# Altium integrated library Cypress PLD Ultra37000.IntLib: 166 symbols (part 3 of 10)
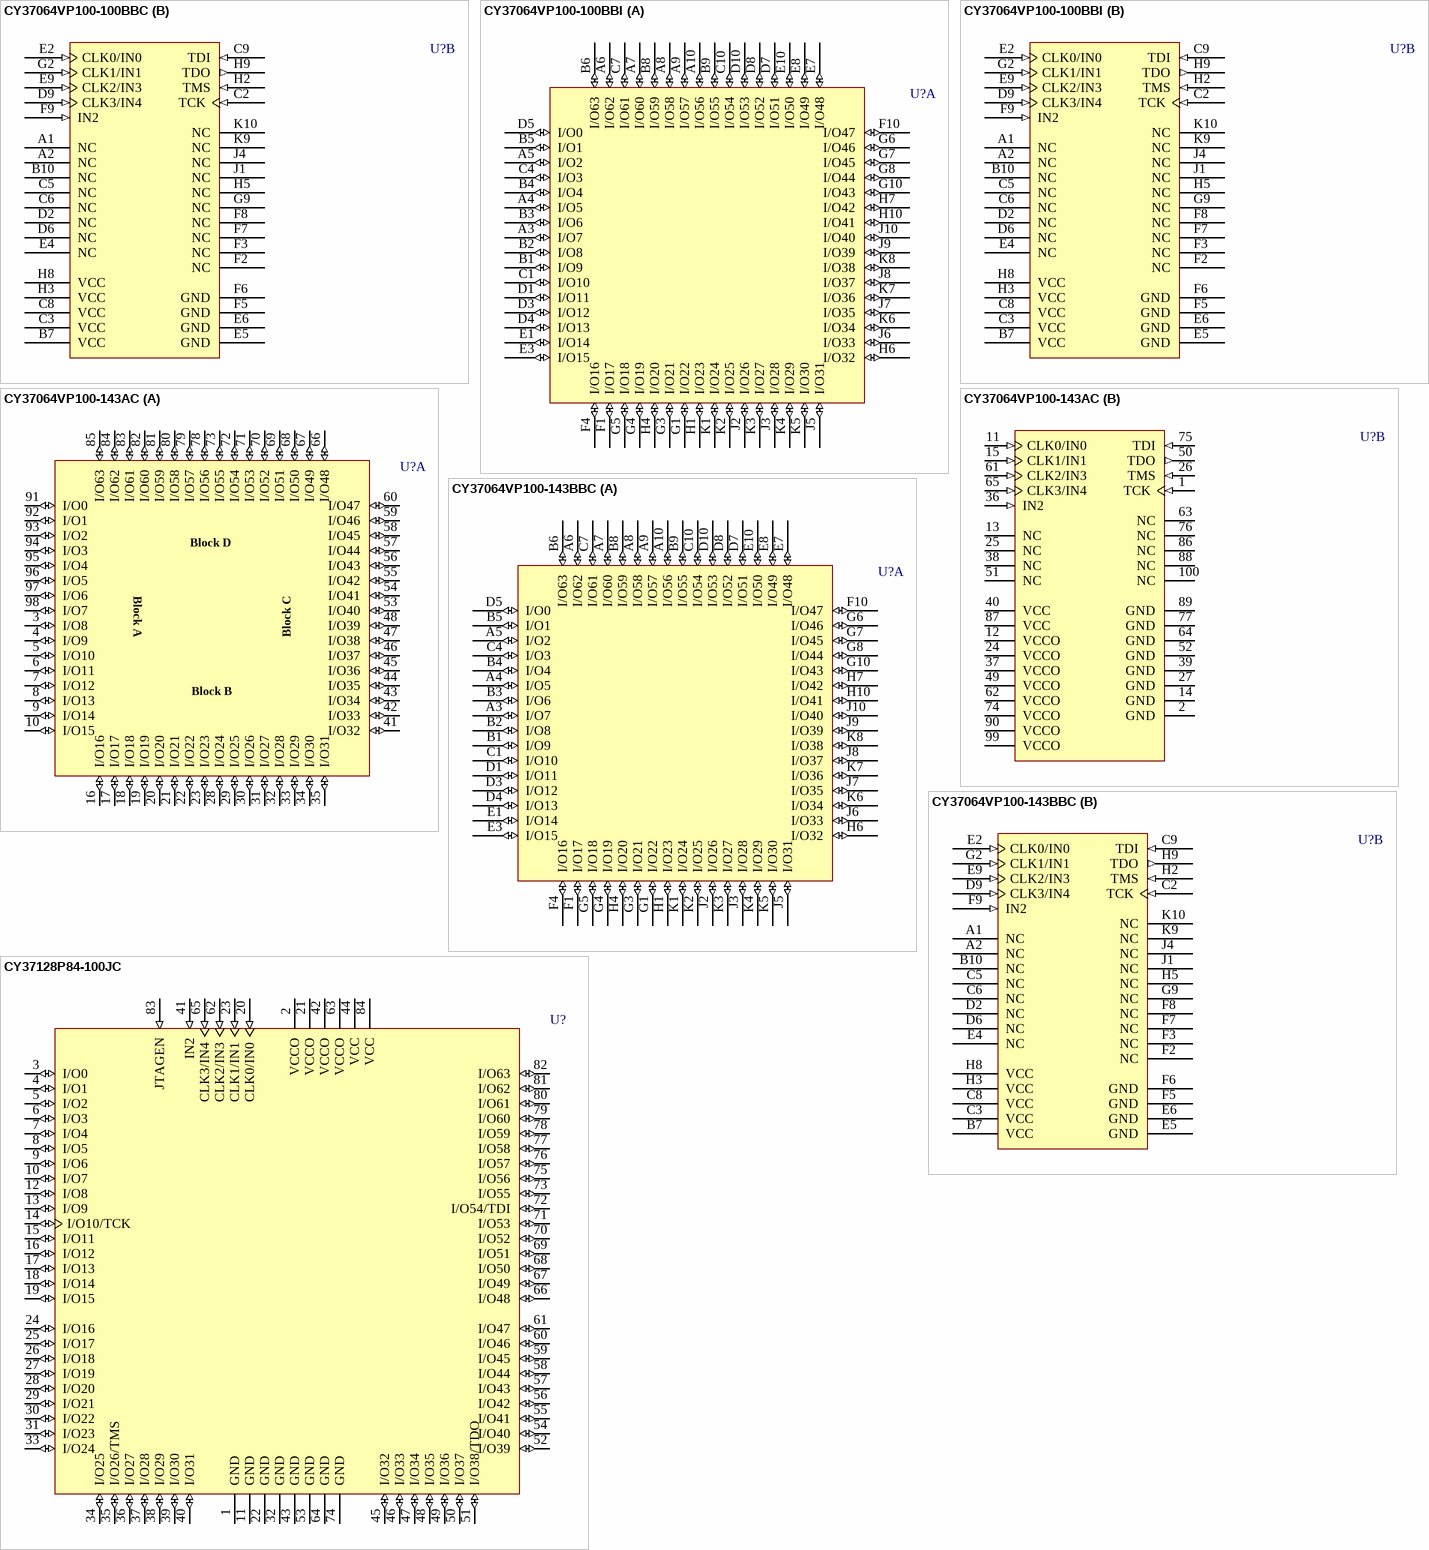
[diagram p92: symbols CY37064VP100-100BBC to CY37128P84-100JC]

## CY37064VP100-143AC
designator U?
Ultra37000 3.3V, ISR High-Performance CPLD
footprint A100_N (Thin QFP, 100-Leads, Body 14x14mm, Pitch 0.5mm, IPC Medium Density)
footprint A100_L (Thin QFP, 100-Leads, Body 14x14mm, Pitch 0.5mm, IPC High Density)
footprint A100_M (Thin QFP, 100-Leads, Body 14x14mm, Pitch 0.5mm, IPC Low Density)
3D model CY37064VP100-A100 (100-Pin Thin Quad Flat Pack 0.5 mm Pitch)
part A pins: 3 I/O8 (io), 4 I/O9 (io), 5 I/O10 (io), 6 I/O11 (io), 7 I/O12 (io), 8 I/O13 (io), 9 I/O14 (io), 10 I/O15 (io), 16 I/O16 (io), 17 I/O17 (io), 18 I/O18 (io), 19 I/O19 (io), 20 I/O20 (io), 21 I/O21 (io), 22 I/O22 (io), 23 I/O23 (io), 28 I/O24 (io), 29 I/O25 (io), 30 I/O26 (io), 31 I/O27 (io), 32 I/O28 (io), 33 I/O29 (io), 34 I/O30 (io), 35 I/O31 (io), 41 I/O32 (io), 42 I/O33 (io), 43 I/O34 (io), 44 I/O35 (io), 45 I/O36 (io), 46 I/O37 (io), 47 I/O38 (io), 48 I/O39 (io), 53 I/O40 (io), 54 I/O41 (io), 55 I/O42 (io), 56 I/O43 (io), 57 I/O44 (io), 58 I/O45 (io), 59 I/O46 (io), 60 I/O47 (io), 66 I/O48 (io), 67 I/O49 (io), 68 I/O50 (io), 69 I/O51 (io), 70 I/O52 (io), 71 I/O53 (io), 72 I/O54 (io), 73 I/O55 (io), 78 I/O56 (io), 79 I/O57 (io), 80 I/O58 (io), 81 I/O59 (io), 82 I/O60 (io), 83 I/O61 (io), 84 I/O62 (io), 85 I/O63 (io), 91 I/O0 (io), 92 I/O1 (io), 93 I/O2 (io), 94 I/O3 (io), 95 I/O4 (io), 96 I/O5 (io), 97 I/O6 (io), 98 I/O7 (io)
part B pins: 1 TCK (in), 2 GND (power), 11 CLK0/IN0 (in), 12 VCCO (power), 13 NC, 14 GND (power), 15 CLK1/IN1 (in), 24 VCCO (power), 25 NC, 26 TMS (in), 27 GND (power), 36 IN2 (in), 37 VCCO (power), 38 NC, 39 GND (power), 40 VCC (power), 49 VCCO (power), 50 TDO (out), 51 NC, 52 GND (power), 61 CLK2/IN3 (in), 62 VCCO (power), 63 NC, 64 GND (power), 65 CLK3/IN4 (in), 74 VCCO (power), 75 TDI (in), 76 NC, 77 GND (power), 86 NC, 87 VCC (power), 88 NC, 89 GND (power), 90 VCCO (power), 99 VCCO (power), 100 NC

## CY37064VP100-143BBC
designator U?
Ultra37000 3.3V, ISR High-Performance CPLD
footprint BB100 (BGA, 100-Leads, Body 11x11mm, Pitch 1mm)
3D model CY37064VP100-BB100 (100-Ball Thin Ball Grid Array 1 mm Pitch)
part A pins: A3 I/O7 (io), A4 I/O5 (io), A5 I/O2 (io), A6 I/O62 (io), A7 I/O60 (io), A8 I/O58 (io), A9 I/O57 (io), A10 I/O56 (io), B1 I/O9 (io), B2 I/O8 (io), B3 I/O6 (io), B4 I/O4 (io), B5 I/O1 (io), B6 I/O63 (io), B8 I/O59 (io), B9 I/O55 (io), C1 I/O10 (io), C4 I/O3 (io), C7 I/O61 (io), C10 I/O54 (io), D1 I/O11 (io), D3 I/O12 (io), D4 I/O13 (io), D5 I/O0 (io), D7 I/O51 (io), D8 I/O52 (io), D10 I/O53 (io), E1 I/O14 (io), E3 I/O15 (io), E7 I/O48 (io), E8 I/O49 (io), E10 I/O50 (io), F1 I/O17 (io), F4 I/O16 (io), F10 I/O47 (io), G1 I/O22 (io), G3 I/O21 (io), G4 I/O19 (io), G5 I/O18 (io), G6 I/O46 (io), G7 I/O45 (io), G8 I/O44 (io), G10 I/O43 (io), H1 I/O23 (io), H4 I/O20 (io), H6 I/O32 (io), H7 I/O42 (io), H10 I/O41 (io), J2 I/O26 (io), J3 I/O28 (io), J5 I/O31 (io), J6 I/O33 (io), J7 I/O35 (io), J8 I/O37 (io), J9 I/O39 (io), J10 I/O40 (io), K1 I/O24 (io), K2 I/O25 (io), K3 I/O27 (io), K4 I/O29 (io), K5 I/O30 (io), K6 I/O34 (io), K7 I/O36 (io), K8 I/O38 (io)
part B pins: A1 NC, A2 NC, B7 VCC (power), B10 NC, C2 TCK (in), C3 VCC (power), C5 NC, C6 NC, C8 VCC (power), C9 TDI (in), D2 NC, D6 NC, D9 CLK3/IN4 (in), E2 CLK0/IN0 (in), E4 NC, E5 GND (power), E6 GND (power), E9 CLK2/IN3 (in), F2 NC, F3 NC, F5 GND (power), F6 GND (power), F7 NC, F8 NC, F9 IN2 (in), G2 CLK1/IN1 (in), G9 NC, H2 TMS (in), H3 VCC (power), H5 NC, H8 VCC (power), H9 TDO (out), J1 NC, J4 NC, K9 NC, K10 NC

## CY37128P84-100JC
designator U?
Ultra37000 5V, ISR High-Performance CPLD
footprint J83_N (Leaded Chip Carrier, 84-Leads, Body 29.3x29.3mm, Pitch 1.27mm, IPC Medium Density)
footprint J83_L (Leaded Chip Carrier, 84-Leads, Body 29.3x29.3mm, Pitch 1.27mm, IPC High Density)
footprint J83_M (Leaded Chip Carrier, 84-Leads, Body 29.3x29.3mm, Pitch 1.27mm, IPC Low Density)
3D model CY37128P84-J83 (84-Pin Plastic Leaded Chip Carrier 1.27 mm Pitch)
pins: 1 GND (power), 2 VCCO (power), 3 I/O0 (io), 4 I/O1 (io), 5 I/O2 (io), 6 I/O3 (io), 7 I/O4 (io), 8 I/O5 (io), 9 I/O6 (io), 10 I/O7 (io), 11 GND (power), 12 I/O8 (io), 13 I/O9 (io), 14 I/O10/TCK (io), 15 I/O11 (io), 16 I/O12 (io), 17 I/O13 (io), 18 I/O14 (io), 19 I/O15 (io), 20 CLK0/IN0 (in), 21 VCCO (power), 22 GND (power), 23 CLK1/IN1 (in), 24 I/O16 (io), 25 I/O17 (io), 26 I/O18 (io), 27 I/O19 (io), 28 I/O20 (io), 29 I/O21 (io), 30 I/O22 (io), 31 I/O23 (io), 32 GND (power), 33 I/O24 (io), 34 I/O25 (io), 35 I/O26/TMS (io), 36 I/O27 (io), 37 I/O28 (io), 38 I/O29 (io), 39 I/O30 (io), 40 I/O31 (io), 41 IN2 (in), 42 VCCO (power), 43 GND (power), 44 VCC (power), 45 I/O32 (io), 46 I/O33 (io), 47 I/O34 (io), 48 I/O35 (io), 49 I/O36 (io), 50 I/O37 (io), 51 I/O38/TDO (io), 52 I/O39 (io), 53 GND (power), 54 I/O40 (io), 55 I/O41 (io), 56 I/O42 (io), 57 I/O43 (io), 58 I/O44 (io), 59 I/O45 (io), 60 I/O46 (io), 61 I/O47 (io), 62 CLK2/IN3 (in), 63 VCCO (power), 64 GND (power), 65 CLK3/IN4 (in), 66 I/O48 (io), 67 I/O49 (io), 68 I/O50 (io), 69 I/O51 (io), 70 I/O52 (io), 71 I/O53 (io), 72 I/O54/TDI (io), 73 I/O55 (io), 74 GND (power), 75 I/O56 (io), 76 I/O57 (io), 77 I/O58 (io), 78 I/O59 (io), 79 I/O60 (io), 80 I/O61 (io), 81 I/O62 (io), 82 I/O63 (io), 83 JTAGEN (in), 84 VCC (power)

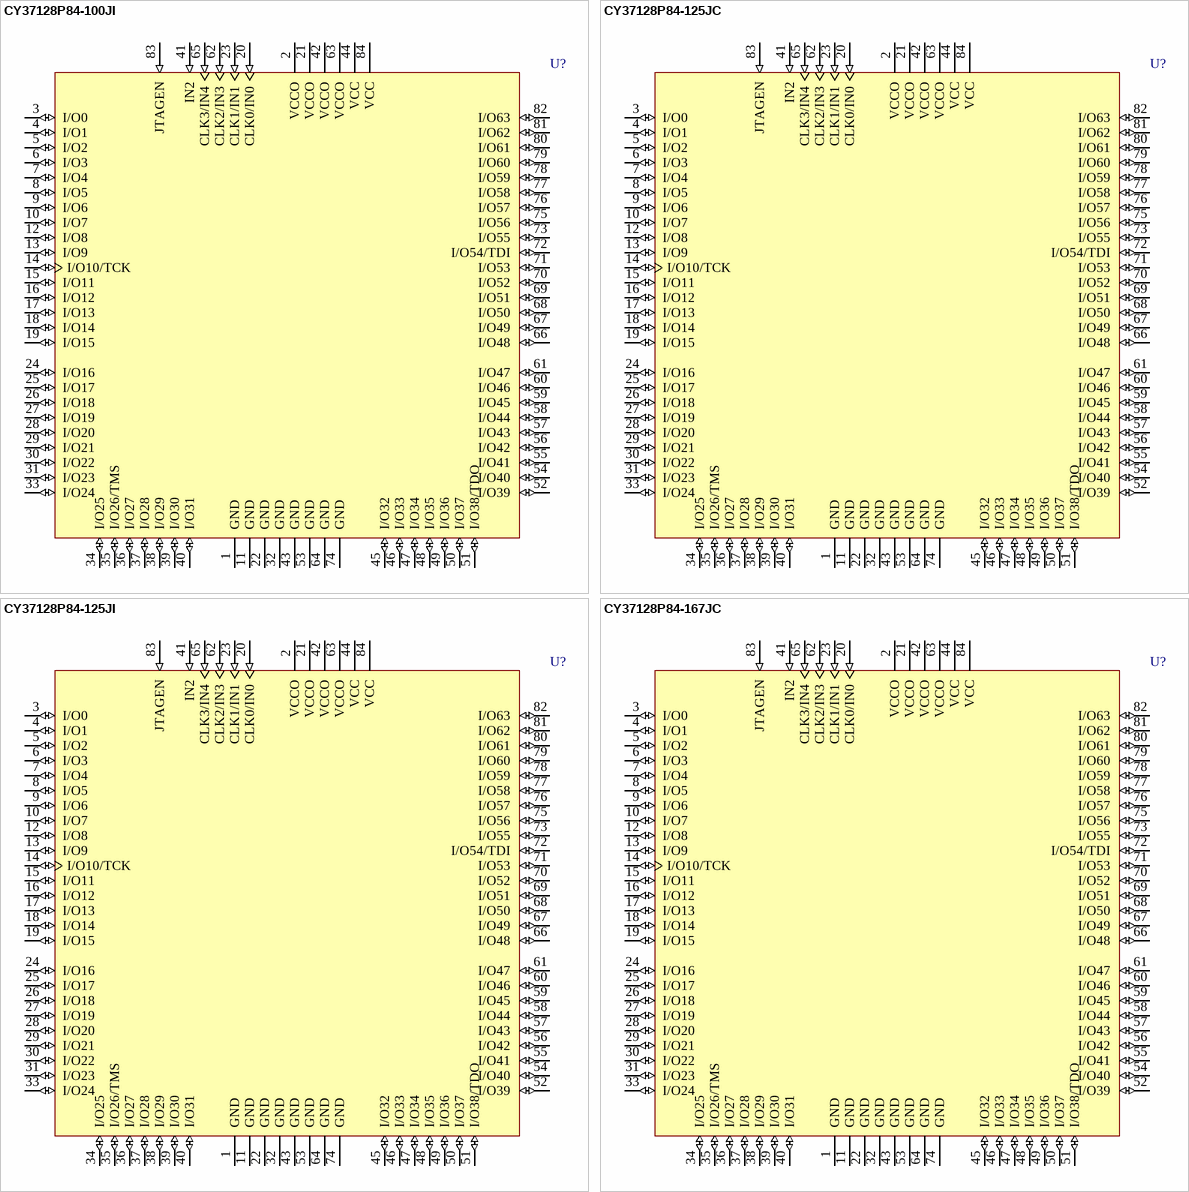
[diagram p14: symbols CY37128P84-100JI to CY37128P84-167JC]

## CY37128P84-100JI
designator U?
Ultra37000 5V, ISR High-Performance CPLD
footprint J83_N (Leaded Chip Carrier, 84-Leads, Body 29.3x29.3mm, Pitch 1.27mm, IPC Medium Density)
footprint J83_L (Leaded Chip Carrier, 84-Leads, Body 29.3x29.3mm, Pitch 1.27mm, IPC High Density)
footprint J83_M (Leaded Chip Carrier, 84-Leads, Body 29.3x29.3mm, Pitch 1.27mm, IPC Low Density)
3D model CY37128P84-J83 (84-Pin Plastic Leaded Chip Carrier 1.27 mm Pitch)
pins: 1 GND (power), 2 VCCO (power), 3 I/O0 (io), 4 I/O1 (io), 5 I/O2 (io), 6 I/O3 (io), 7 I/O4 (io), 8 I/O5 (io), 9 I/O6 (io), 10 I/O7 (io), 11 GND (power), 12 I/O8 (io), 13 I/O9 (io), 14 I/O10/TCK (io), 15 I/O11 (io), 16 I/O12 (io), 17 I/O13 (io), 18 I/O14 (io), 19 I/O15 (io), 20 CLK0/IN0 (in), 21 VCCO (power), 22 GND (power), 23 CLK1/IN1 (in), 24 I/O16 (io), 25 I/O17 (io), 26 I/O18 (io), 27 I/O19 (io), 28 I/O20 (io), 29 I/O21 (io), 30 I/O22 (io), 31 I/O23 (io), 32 GND (power), 33 I/O24 (io), 34 I/O25 (io), 35 I/O26/TMS (io), 36 I/O27 (io), 37 I/O28 (io), 38 I/O29 (io), 39 I/O30 (io), 40 I/O31 (io), 41 IN2 (in), 42 VCCO (power), 43 GND (power), 44 VCC (power), 45 I/O32 (io), 46 I/O33 (io), 47 I/O34 (io), 48 I/O35 (io), 49 I/O36 (io), 50 I/O37 (io), 51 I/O38/TDO (io), 52 I/O39 (io), 53 GND (power), 54 I/O40 (io), 55 I/O41 (io), 56 I/O42 (io), 57 I/O43 (io), 58 I/O44 (io), 59 I/O45 (io), 60 I/O46 (io), 61 I/O47 (io), 62 CLK2/IN3 (in), 63 VCCO (power), 64 GND (power), 65 CLK3/IN4 (in), 66 I/O48 (io), 67 I/O49 (io), 68 I/O50 (io), 69 I/O51 (io), 70 I/O52 (io), 71 I/O53 (io), 72 I/O54/TDI (io), 73 I/O55 (io), 74 GND (power), 75 I/O56 (io), 76 I/O57 (io), 77 I/O58 (io), 78 I/O59 (io), 79 I/O60 (io), 80 I/O61 (io), 81 I/O62 (io), 82 I/O63 (io), 83 JTAGEN (in), 84 VCC (power)

## CY37128P84-125JC
designator U?
Ultra37000 5V, ISR High-Performance CPLD
footprint J83_N (Leaded Chip Carrier, 84-Leads, Body 29.3x29.3mm, Pitch 1.27mm, IPC Medium Density)
footprint J83_L (Leaded Chip Carrier, 84-Leads, Body 29.3x29.3mm, Pitch 1.27mm, IPC High Density)
footprint J83_M (Leaded Chip Carrier, 84-Leads, Body 29.3x29.3mm, Pitch 1.27mm, IPC Low Density)
3D model CY37128P84-J83 (84-Pin Plastic Leaded Chip Carrier 1.27 mm Pitch)
pins: 1 GND (power), 2 VCCO (power), 3 I/O0 (io), 4 I/O1 (io), 5 I/O2 (io), 6 I/O3 (io), 7 I/O4 (io), 8 I/O5 (io), 9 I/O6 (io), 10 I/O7 (io), 11 GND (power), 12 I/O8 (io), 13 I/O9 (io), 14 I/O10/TCK (io), 15 I/O11 (io), 16 I/O12 (io), 17 I/O13 (io), 18 I/O14 (io), 19 I/O15 (io), 20 CLK0/IN0 (in), 21 VCCO (power), 22 GND (power), 23 CLK1/IN1 (in), 24 I/O16 (io), 25 I/O17 (io), 26 I/O18 (io), 27 I/O19 (io), 28 I/O20 (io), 29 I/O21 (io), 30 I/O22 (io), 31 I/O23 (io), 32 GND (power), 33 I/O24 (io), 34 I/O25 (io), 35 I/O26/TMS (io), 36 I/O27 (io), 37 I/O28 (io), 38 I/O29 (io), 39 I/O30 (io), 40 I/O31 (io), 41 IN2 (in), 42 VCCO (power), 43 GND (power), 44 VCC (power), 45 I/O32 (io), 46 I/O33 (io), 47 I/O34 (io), 48 I/O35 (io), 49 I/O36 (io), 50 I/O37 (io), 51 I/O38/TDO (io), 52 I/O39 (io), 53 GND (power), 54 I/O40 (io), 55 I/O41 (io), 56 I/O42 (io), 57 I/O43 (io), 58 I/O44 (io), 59 I/O45 (io), 60 I/O46 (io), 61 I/O47 (io), 62 CLK2/IN3 (in), 63 VCCO (power), 64 GND (power), 65 CLK3/IN4 (in), 66 I/O48 (io), 67 I/O49 (io), 68 I/O50 (io), 69 I/O51 (io), 70 I/O52 (io), 71 I/O53 (io), 72 I/O54/TDI (io), 73 I/O55 (io), 74 GND (power), 75 I/O56 (io), 76 I/O57 (io), 77 I/O58 (io), 78 I/O59 (io), 79 I/O60 (io), 80 I/O61 (io), 81 I/O62 (io), 82 I/O63 (io), 83 JTAGEN (in), 84 VCC (power)

## CY37128P84-125JI
designator U?
Ultra37000 5V, ISR High-Performance CPLD
footprint J83_N (Leaded Chip Carrier, 84-Leads, Body 29.3x29.3mm, Pitch 1.27mm, IPC Medium Density)
footprint J83_L (Leaded Chip Carrier, 84-Leads, Body 29.3x29.3mm, Pitch 1.27mm, IPC High Density)
footprint J83_M (Leaded Chip Carrier, 84-Leads, Body 29.3x29.3mm, Pitch 1.27mm, IPC Low Density)
3D model CY37128P84-J83 (84-Pin Plastic Leaded Chip Carrier 1.27 mm Pitch)
pins: 1 GND (power), 2 VCCO (power), 3 I/O0 (io), 4 I/O1 (io), 5 I/O2 (io), 6 I/O3 (io), 7 I/O4 (io), 8 I/O5 (io), 9 I/O6 (io), 10 I/O7 (io), 11 GND (power), 12 I/O8 (io), 13 I/O9 (io), 14 I/O10/TCK (io), 15 I/O11 (io), 16 I/O12 (io), 17 I/O13 (io), 18 I/O14 (io), 19 I/O15 (io), 20 CLK0/IN0 (in), 21 VCCO (power), 22 GND (power), 23 CLK1/IN1 (in), 24 I/O16 (io), 25 I/O17 (io), 26 I/O18 (io), 27 I/O19 (io), 28 I/O20 (io), 29 I/O21 (io), 30 I/O22 (io), 31 I/O23 (io), 32 GND (power), 33 I/O24 (io), 34 I/O25 (io), 35 I/O26/TMS (io), 36 I/O27 (io), 37 I/O28 (io), 38 I/O29 (io), 39 I/O30 (io), 40 I/O31 (io), 41 IN2 (in), 42 VCCO (power), 43 GND (power), 44 VCC (power), 45 I/O32 (io), 46 I/O33 (io), 47 I/O34 (io), 48 I/O35 (io), 49 I/O36 (io), 50 I/O37 (io), 51 I/O38/TDO (io), 52 I/O39 (io), 53 GND (power), 54 I/O40 (io), 55 I/O41 (io), 56 I/O42 (io), 57 I/O43 (io), 58 I/O44 (io), 59 I/O45 (io), 60 I/O46 (io), 61 I/O47 (io), 62 CLK2/IN3 (in), 63 VCCO (power), 64 GND (power), 65 CLK3/IN4 (in), 66 I/O48 (io), 67 I/O49 (io), 68 I/O50 (io), 69 I/O51 (io), 70 I/O52 (io), 71 I/O53 (io), 72 I/O54/TDI (io), 73 I/O55 (io), 74 GND (power), 75 I/O56 (io), 76 I/O57 (io), 77 I/O58 (io), 78 I/O59 (io), 79 I/O60 (io), 80 I/O61 (io), 81 I/O62 (io), 82 I/O63 (io), 83 JTAGEN (in), 84 VCC (power)

## CY37128P84-167JC
designator U?
Ultra37000 5V, ISR High-Performance CPLD
footprint J83_N (Leaded Chip Carrier, 84-Leads, Body 29.3x29.3mm, Pitch 1.27mm, IPC Medium Density)
footprint J83_L (Leaded Chip Carrier, 84-Leads, Body 29.3x29.3mm, Pitch 1.27mm, IPC High Density)
footprint J83_M (Leaded Chip Carrier, 84-Leads, Body 29.3x29.3mm, Pitch 1.27mm, IPC Low Density)
3D model CY37128P84-J83 (84-Pin Plastic Leaded Chip Carrier 1.27 mm Pitch)
pins: 1 GND (power), 2 VCCO (power), 3 I/O0 (io), 4 I/O1 (io), 5 I/O2 (io), 6 I/O3 (io), 7 I/O4 (io), 8 I/O5 (io), 9 I/O6 (io), 10 I/O7 (io), 11 GND (power), 12 I/O8 (io), 13 I/O9 (io), 14 I/O10/TCK (io), 15 I/O11 (io), 16 I/O12 (io), 17 I/O13 (io), 18 I/O14 (io), 19 I/O15 (io), 20 CLK0/IN0 (in), 21 VCCO (power), 22 GND (power), 23 CLK1/IN1 (in), 24 I/O16 (io), 25 I/O17 (io), 26 I/O18 (io), 27 I/O19 (io), 28 I/O20 (io), 29 I/O21 (io), 30 I/O22 (io), 31 I/O23 (io), 32 GND (power), 33 I/O24 (io), 34 I/O25 (io), 35 I/O26/TMS (io), 36 I/O27 (io), 37 I/O28 (io), 38 I/O29 (io), 39 I/O30 (io), 40 I/O31 (io), 41 IN2 (in), 42 VCCO (power), 43 GND (power), 44 VCC (power), 45 I/O32 (io), 46 I/O33 (io), 47 I/O34 (io), 48 I/O35 (io), 49 I/O36 (io), 50 I/O37 (io), 51 I/O38/TDO (io), 52 I/O39 (io), 53 GND (power), 54 I/O40 (io), 55 I/O41 (io), 56 I/O42 (io), 57 I/O43 (io), 58 I/O44 (io), 59 I/O45 (io), 60 I/O46 (io), 61 I/O47 (io), 62 CLK2/IN3 (in), 63 VCCO (power), 64 GND (power), 65 CLK3/IN4 (in), 66 I/O48 (io), 67 I/O49 (io), 68 I/O50 (io), 69 I/O51 (io), 70 I/O52 (io), 71 I/O53 (io), 72 I/O54/TDI (io), 73 I/O55 (io), 74 GND (power), 75 I/O56 (io), 76 I/O57 (io), 77 I/O58 (io), 78 I/O59 (io), 79 I/O60 (io), 80 I/O61 (io), 81 I/O62 (io), 82 I/O63 (io), 83 JTAGEN (in), 84 VCC (power)

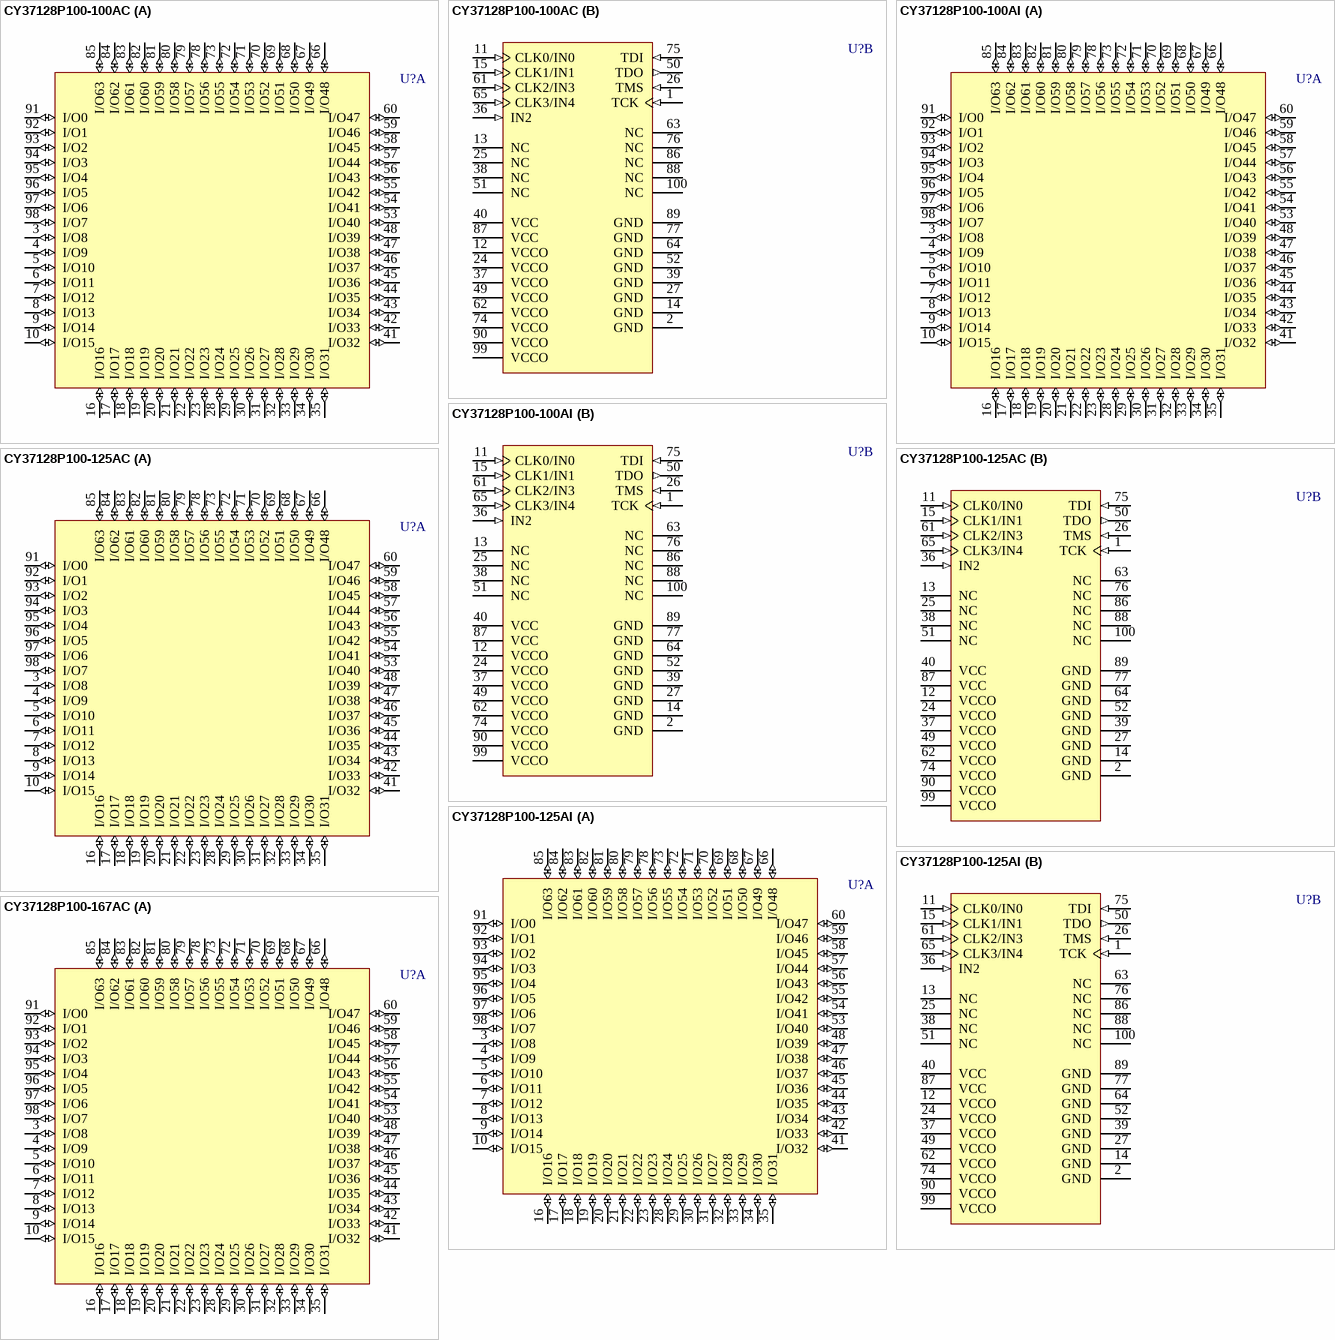
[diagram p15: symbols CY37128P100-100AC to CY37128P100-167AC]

## CY37128P100-100AC
designator U?
Ultra37000 5V, ISR High-Performance CPLD
footprint A100_N (Thin QFP, 100-Leads, Body 14x14mm, Pitch 0.5mm, IPC Medium Density)
footprint A100_L (Thin QFP, 100-Leads, Body 14x14mm, Pitch 0.5mm, IPC High Density)
footprint A100_M (Thin QFP, 100-Leads, Body 14x14mm, Pitch 0.5mm, IPC Low Density)
3D model CY37128P100-A100 (100-Pin Thin Quad Flat Pack 0.5 mm Pitch)
part A pins: 3 I/O8 (io), 4 I/O9 (io), 5 I/O10 (io), 6 I/O11 (io), 7 I/O12 (io), 8 I/O13 (io), 9 I/O14 (io), 10 I/O15 (io), 16 I/O16 (io), 17 I/O17 (io), 18 I/O18 (io), 19 I/O19 (io), 20 I/O20 (io), 21 I/O21 (io), 22 I/O22 (io), 23 I/O23 (io), 28 I/O24 (io), 29 I/O25 (io), 30 I/O26 (io), 31 I/O27 (io), 32 I/O28 (io), 33 I/O29 (io), 34 I/O30 (io), 35 I/O31 (io), 41 I/O32 (io), 42 I/O33 (io), 43 I/O34 (io), 44 I/O35 (io), 45 I/O36 (io), 46 I/O37 (io), 47 I/O38 (io), 48 I/O39 (io), 53 I/O40 (io), 54 I/O41 (io), 55 I/O42 (io), 56 I/O43 (io), 57 I/O44 (io), 58 I/O45 (io), 59 I/O46 (io), 60 I/O47 (io), 66 I/O48 (io), 67 I/O49 (io), 68 I/O50 (io), 69 I/O51 (io), 70 I/O52 (io), 71 I/O53 (io), 72 I/O54 (io), 73 I/O55 (io), 78 I/O56 (io), 79 I/O57 (io), 80 I/O58 (io), 81 I/O59 (io), 82 I/O60 (io), 83 I/O61 (io), 84 I/O62 (io), 85 I/O63 (io), 91 I/O0 (io), 92 I/O1 (io), 93 I/O2 (io), 94 I/O3 (io), 95 I/O4 (io), 96 I/O5 (io), 97 I/O6 (io), 98 I/O7 (io)
part B pins: 1 TCK (in), 2 GND (power), 11 CLK0/IN0 (in), 12 VCCO (power), 13 NC, 14 GND (power), 15 CLK1/IN1 (in), 24 VCCO (power), 25 NC, 26 TMS (in), 27 GND (power), 36 IN2 (in), 37 VCCO (power), 38 NC, 39 GND (power), 40 VCC (power), 49 VCCO (power), 50 TDO (out), 51 NC, 52 GND (power), 61 CLK2/IN3 (in), 62 VCCO (power), 63 NC, 64 GND (power), 65 CLK3/IN4 (in), 74 VCCO (power), 75 TDI (in), 76 NC, 77 GND (power), 86 NC, 87 VCC (power), 88 NC, 89 GND (power), 90 VCCO (power), 99 VCCO (power), 100 NC

## CY37128P100-100AI
designator U?
Ultra37000 5V, ISR High-Performance CPLD
footprint A100_N (Thin QFP, 100-Leads, Body 14x14mm, Pitch 0.5mm, IPC Medium Density)
footprint A100_L (Thin QFP, 100-Leads, Body 14x14mm, Pitch 0.5mm, IPC High Density)
footprint A100_M (Thin QFP, 100-Leads, Body 14x14mm, Pitch 0.5mm, IPC Low Density)
3D model CY37128P100-A100 (100-Pin Thin Quad Flat Pack 0.5 mm Pitch)
part A pins: 3 I/O8 (io), 4 I/O9 (io), 5 I/O10 (io), 6 I/O11 (io), 7 I/O12 (io), 8 I/O13 (io), 9 I/O14 (io), 10 I/O15 (io), 16 I/O16 (io), 17 I/O17 (io), 18 I/O18 (io), 19 I/O19 (io), 20 I/O20 (io), 21 I/O21 (io), 22 I/O22 (io), 23 I/O23 (io), 28 I/O24 (io), 29 I/O25 (io), 30 I/O26 (io), 31 I/O27 (io), 32 I/O28 (io), 33 I/O29 (io), 34 I/O30 (io), 35 I/O31 (io), 41 I/O32 (io), 42 I/O33 (io), 43 I/O34 (io), 44 I/O35 (io), 45 I/O36 (io), 46 I/O37 (io), 47 I/O38 (io), 48 I/O39 (io), 53 I/O40 (io), 54 I/O41 (io), 55 I/O42 (io), 56 I/O43 (io), 57 I/O44 (io), 58 I/O45 (io), 59 I/O46 (io), 60 I/O47 (io), 66 I/O48 (io), 67 I/O49 (io), 68 I/O50 (io), 69 I/O51 (io), 70 I/O52 (io), 71 I/O53 (io), 72 I/O54 (io), 73 I/O55 (io), 78 I/O56 (io), 79 I/O57 (io), 80 I/O58 (io), 81 I/O59 (io), 82 I/O60 (io), 83 I/O61 (io), 84 I/O62 (io), 85 I/O63 (io), 91 I/O0 (io), 92 I/O1 (io), 93 I/O2 (io), 94 I/O3 (io), 95 I/O4 (io), 96 I/O5 (io), 97 I/O6 (io), 98 I/O7 (io)
part B pins: 1 TCK (in), 2 GND (power), 11 CLK0/IN0 (in), 12 VCCO (power), 13 NC, 14 GND (power), 15 CLK1/IN1 (in), 24 VCCO (power), 25 NC, 26 TMS (in), 27 GND (power), 36 IN2 (in), 37 VCCO (power), 38 NC, 39 GND (power), 40 VCC (power), 49 VCCO (power), 50 TDO (out), 51 NC, 52 GND (power), 61 CLK2/IN3 (in), 62 VCCO (power), 63 NC, 64 GND (power), 65 CLK3/IN4 (in), 74 VCCO (power), 75 TDI (in), 76 NC, 77 GND (power), 86 NC, 87 VCC (power), 88 NC, 89 GND (power), 90 VCCO (power), 99 VCCO (power), 100 NC

## CY37128P100-125AC
designator U?
Ultra37000 5V, ISR High-Performance CPLD
footprint A100_N (Thin QFP, 100-Leads, Body 14x14mm, Pitch 0.5mm, IPC Medium Density)
footprint A100_L (Thin QFP, 100-Leads, Body 14x14mm, Pitch 0.5mm, IPC High Density)
footprint A100_M (Thin QFP, 100-Leads, Body 14x14mm, Pitch 0.5mm, IPC Low Density)
3D model CY37128P100-A100 (100-Pin Thin Quad Flat Pack 0.5 mm Pitch)
part A pins: 3 I/O8 (io), 4 I/O9 (io), 5 I/O10 (io), 6 I/O11 (io), 7 I/O12 (io), 8 I/O13 (io), 9 I/O14 (io), 10 I/O15 (io), 16 I/O16 (io), 17 I/O17 (io), 18 I/O18 (io), 19 I/O19 (io), 20 I/O20 (io), 21 I/O21 (io), 22 I/O22 (io), 23 I/O23 (io), 28 I/O24 (io), 29 I/O25 (io), 30 I/O26 (io), 31 I/O27 (io), 32 I/O28 (io), 33 I/O29 (io), 34 I/O30 (io), 35 I/O31 (io), 41 I/O32 (io), 42 I/O33 (io), 43 I/O34 (io), 44 I/O35 (io), 45 I/O36 (io), 46 I/O37 (io), 47 I/O38 (io), 48 I/O39 (io), 53 I/O40 (io), 54 I/O41 (io), 55 I/O42 (io), 56 I/O43 (io), 57 I/O44 (io), 58 I/O45 (io), 59 I/O46 (io), 60 I/O47 (io), 66 I/O48 (io), 67 I/O49 (io), 68 I/O50 (io), 69 I/O51 (io), 70 I/O52 (io), 71 I/O53 (io), 72 I/O54 (io), 73 I/O55 (io), 78 I/O56 (io), 79 I/O57 (io), 80 I/O58 (io), 81 I/O59 (io), 82 I/O60 (io), 83 I/O61 (io), 84 I/O62 (io), 85 I/O63 (io), 91 I/O0 (io), 92 I/O1 (io), 93 I/O2 (io), 94 I/O3 (io), 95 I/O4 (io), 96 I/O5 (io), 97 I/O6 (io), 98 I/O7 (io)
part B pins: 1 TCK (in), 2 GND (power), 11 CLK0/IN0 (in), 12 VCCO (power), 13 NC, 14 GND (power), 15 CLK1/IN1 (in), 24 VCCO (power), 25 NC, 26 TMS (in), 27 GND (power), 36 IN2 (in), 37 VCCO (power), 38 NC, 39 GND (power), 40 VCC (power), 49 VCCO (power), 50 TDO (out), 51 NC, 52 GND (power), 61 CLK2/IN3 (in), 62 VCCO (power), 63 NC, 64 GND (power), 65 CLK3/IN4 (in), 74 VCCO (power), 75 TDI (in), 76 NC, 77 GND (power), 86 NC, 87 VCC (power), 88 NC, 89 GND (power), 90 VCCO (power), 99 VCCO (power), 100 NC

## CY37128P100-125AI
designator U?
Ultra37000 5V, ISR High-Performance CPLD
footprint A100_N (Thin QFP, 100-Leads, Body 14x14mm, Pitch 0.5mm, IPC Medium Density)
footprint A100_L (Thin QFP, 100-Leads, Body 14x14mm, Pitch 0.5mm, IPC High Density)
footprint A100_M (Thin QFP, 100-Leads, Body 14x14mm, Pitch 0.5mm, IPC Low Density)
3D model CY37128P100-A100 (100-Pin Thin Quad Flat Pack 0.5 mm Pitch)
part A pins: 3 I/O8 (io), 4 I/O9 (io), 5 I/O10 (io), 6 I/O11 (io), 7 I/O12 (io), 8 I/O13 (io), 9 I/O14 (io), 10 I/O15 (io), 16 I/O16 (io), 17 I/O17 (io), 18 I/O18 (io), 19 I/O19 (io), 20 I/O20 (io), 21 I/O21 (io), 22 I/O22 (io), 23 I/O23 (io), 28 I/O24 (io), 29 I/O25 (io), 30 I/O26 (io), 31 I/O27 (io), 32 I/O28 (io), 33 I/O29 (io), 34 I/O30 (io), 35 I/O31 (io), 41 I/O32 (io), 42 I/O33 (io), 43 I/O34 (io), 44 I/O35 (io), 45 I/O36 (io), 46 I/O37 (io), 47 I/O38 (io), 48 I/O39 (io), 53 I/O40 (io), 54 I/O41 (io), 55 I/O42 (io), 56 I/O43 (io), 57 I/O44 (io), 58 I/O45 (io), 59 I/O46 (io), 60 I/O47 (io), 66 I/O48 (io), 67 I/O49 (io), 68 I/O50 (io), 69 I/O51 (io), 70 I/O52 (io), 71 I/O53 (io), 72 I/O54 (io), 73 I/O55 (io), 78 I/O56 (io), 79 I/O57 (io), 80 I/O58 (io), 81 I/O59 (io), 82 I/O60 (io), 83 I/O61 (io), 84 I/O62 (io), 85 I/O63 (io), 91 I/O0 (io), 92 I/O1 (io), 93 I/O2 (io), 94 I/O3 (io), 95 I/O4 (io), 96 I/O5 (io), 97 I/O6 (io), 98 I/O7 (io)
part B pins: 1 TCK (in), 2 GND (power), 11 CLK0/IN0 (in), 12 VCCO (power), 13 NC, 14 GND (power), 15 CLK1/IN1 (in), 24 VCCO (power), 25 NC, 26 TMS (in), 27 GND (power), 36 IN2 (in), 37 VCCO (power), 38 NC, 39 GND (power), 40 VCC (power), 49 VCCO (power), 50 TDO (out), 51 NC, 52 GND (power), 61 CLK2/IN3 (in), 62 VCCO (power), 63 NC, 64 GND (power), 65 CLK3/IN4 (in), 74 VCCO (power), 75 TDI (in), 76 NC, 77 GND (power), 86 NC, 87 VCC (power), 88 NC, 89 GND (power), 90 VCCO (power), 99 VCCO (power), 100 NC

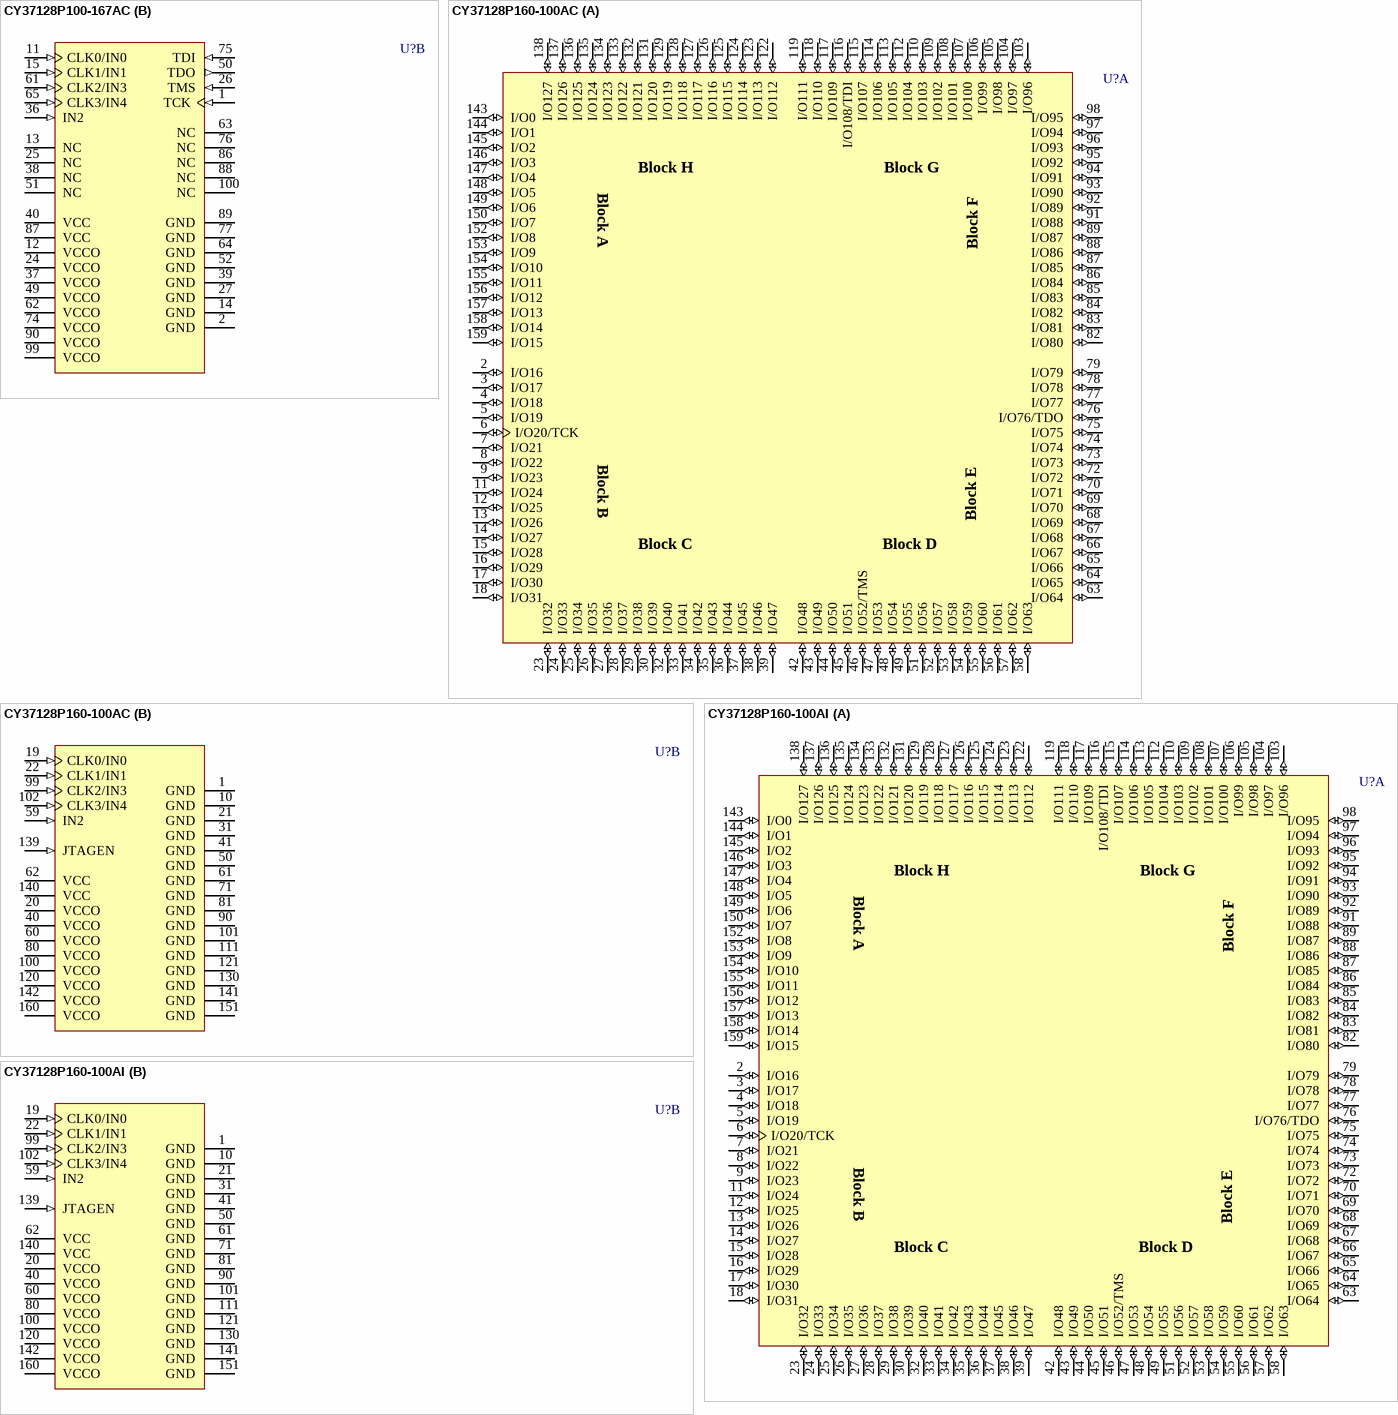
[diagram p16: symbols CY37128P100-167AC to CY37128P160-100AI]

## CY37128P100-167AC
designator U?
Ultra37000 5V, ISR High-Performance CPLD
footprint A100_N (Thin QFP, 100-Leads, Body 14x14mm, Pitch 0.5mm, IPC Medium Density)
footprint A100_L (Thin QFP, 100-Leads, Body 14x14mm, Pitch 0.5mm, IPC High Density)
footprint A100_M (Thin QFP, 100-Leads, Body 14x14mm, Pitch 0.5mm, IPC Low Density)
3D model CY37128P100-A100 (100-Pin Thin Quad Flat Pack 0.5 mm Pitch)
part A pins: 3 I/O8 (io), 4 I/O9 (io), 5 I/O10 (io), 6 I/O11 (io), 7 I/O12 (io), 8 I/O13 (io), 9 I/O14 (io), 10 I/O15 (io), 16 I/O16 (io), 17 I/O17 (io), 18 I/O18 (io), 19 I/O19 (io), 20 I/O20 (io), 21 I/O21 (io), 22 I/O22 (io), 23 I/O23 (io), 28 I/O24 (io), 29 I/O25 (io), 30 I/O26 (io), 31 I/O27 (io), 32 I/O28 (io), 33 I/O29 (io), 34 I/O30 (io), 35 I/O31 (io), 41 I/O32 (io), 42 I/O33 (io), 43 I/O34 (io), 44 I/O35 (io), 45 I/O36 (io), 46 I/O37 (io), 47 I/O38 (io), 48 I/O39 (io), 53 I/O40 (io), 54 I/O41 (io), 55 I/O42 (io), 56 I/O43 (io), 57 I/O44 (io), 58 I/O45 (io), 59 I/O46 (io), 60 I/O47 (io), 66 I/O48 (io), 67 I/O49 (io), 68 I/O50 (io), 69 I/O51 (io), 70 I/O52 (io), 71 I/O53 (io), 72 I/O54 (io), 73 I/O55 (io), 78 I/O56 (io), 79 I/O57 (io), 80 I/O58 (io), 81 I/O59 (io), 82 I/O60 (io), 83 I/O61 (io), 84 I/O62 (io), 85 I/O63 (io), 91 I/O0 (io), 92 I/O1 (io), 93 I/O2 (io), 94 I/O3 (io), 95 I/O4 (io), 96 I/O5 (io), 97 I/O6 (io), 98 I/O7 (io)
part B pins: 1 TCK (in), 2 GND (power), 11 CLK0/IN0 (in), 12 VCCO (power), 13 NC, 14 GND (power), 15 CLK1/IN1 (in), 24 VCCO (power), 25 NC, 26 TMS (in), 27 GND (power), 36 IN2 (in), 37 VCCO (power), 38 NC, 39 GND (power), 40 VCC (power), 49 VCCO (power), 50 TDO (out), 51 NC, 52 GND (power), 61 CLK2/IN3 (in), 62 VCCO (power), 63 NC, 64 GND (power), 65 CLK3/IN4 (in), 74 VCCO (power), 75 TDI (in), 76 NC, 77 GND (power), 86 NC, 87 VCC (power), 88 NC, 89 GND (power), 90 VCCO (power), 99 VCCO (power), 100 NC

## CY37128P160-100AC
designator U?
Ultra37000 5V, ISR High-Performance CPLD
footprint A160_N (Thin QFP, 160-Leads, Body 24x24mm, Pitch 0.5mm, IPC Medium Density)
footprint A160_L (Thin QFP, 160-Leads, Body 24x24mm, Pitch 0.5mm, IPC High Density)
footprint A160_M (Thin QFP, 160-Leads, Body 24x24mm, Pitch 0.5mm, IPC Low Density)
3D model CY37128P160-A160 (160-Pin Thin Quad Flat Pack 0.5 mm Pitch)
part A pins: 2 I/O16 (io), 3 I/O17 (io), 4 I/O18 (io), 5 I/O19 (io), 6 I/O20/TCK (io), 7 I/O21 (io), 8 I/O22 (io), 9 I/O23 (io), 11 I/O24 (io), 12 I/O25 (io), 13 I/O26 (io), 14 I/O27 (io), 15 I/O28 (io), 16 I/O29 (io), 17 I/O30 (io), 18 I/O31 (io), 23 I/O32 (io), 24 I/O33 (io), 25 I/O34 (io), 26 I/O35 (io), 27 I/O36 (io), 28 I/O37 (io), 29 I/O38 (io), 30 I/O39 (io), 32 I/O40 (io), 33 I/O41 (io), 34 I/O42 (io), 35 I/O43 (io), 36 I/O44 (io), 37 I/O45 (io), 38 I/O46 (io), 39 I/O47 (io), 42 I/O48 (io), 43 I/O49 (io), 44 I/O50 (io), 45 I/O51 (io), 46 I/O52/TMS (io), 47 I/O53 (io), 48 I/O54 (io), 49 I/O55 (io), 51 I/O56 (io), 52 I/O57 (io), 53 I/O58 (io), 54 I/O59 (io), 55 I/O60 (io), 56 I/O61 (io), 57 I/O62 (io), 58 I/O63 (io), 63 I/O64 (io), 64 I/O65 (io), 65 I/O66 (io), 66 I/O67 (io), 67 I/O68 (io), 68 I/O69 (io), 69 I/O70 (io), 70 I/O71 (io), 72 I/O72 (io), 73 I/O73 (io), 74 I/O74 (io), 75 I/O75 (io), 76 I/O76/TDO (io), 77 I/O77 (io), 78 I/O78 (io), 79 I/O79 (io), 82 I/O80 (io), 83 I/O81 (io), 84 I/O82 (io), 85 I/O83 (io), 86 I/O84 (io), 87 I/O85 (io), 88 I/O86 (io), 89 I/O87 (io), 91 I/O88 (io), 92 I/O89 (io), 93 I/O90 (io), 94 I/O91 (io), 95 I/O92 (io), 96 I/O93 (io), 97 I/O94 (io), 98 I/O95 (io), 103 I/O96 (io), 104 I/O97 (io), 105 I/O98 (io), 106 I/O99 (io), 107 I/O100 (io), 108 I/O101 (io), 109 I/O102 (io), 110 I/O103 (io), 112 I/O104 (io), 113 I/O105 (io), 114 I/O106 (io), 115 I/O107 (io), 116 I/O108/TDI (io), 117 I/O109 (io), 118 I/O110 (io), 119 I/O111 (io), 122 I/O112 (io), 123 I/O113 (io), 124 I/O114 (io), 125 I/O115 (io), 126 I/O116 (io), 127 I/O117 (io), 128 I/O118 (io), 129 I/O119 (io), 131 I/O120 (io), 132 I/O121 (io), 133 I/O122 (io), 134 I/O123 (io), 135 I/O124 (io), 136 I/O125 (io), 137 I/O126 (io), 138 I/O127 (io), 143 I/O0 (io), 144 I/O1 (io), 145 I/O2 (io), 146 I/O3 (io), 147 I/O4 (io), 148 I/O5 (io), 149 I/O6 (io), 150 I/O7 (io), 152 I/O8 (io), 153 I/O9 (io), 154 I/O10 (io), 155 I/O11 (io), 156 I/O12 (io), 157 I/O13 (io), 158 I/O14 (io), 159 I/O15 (io)
part B pins: 1 GND (power), 10 GND (power), 19 CLK0/IN0 (in), 20 VCCO (power), 21 GND (power), 22 CLK1/IN1 (in), 31 GND (power), 40 VCCO (power), 41 GND (power), 50 GND (power), 59 IN2 (in), 60 VCCO (power), 61 GND (power), 62 VCC (power), 71 GND (power), 80 VCCO (power), 81 GND (power), 90 GND (power), 99 CLK2/IN3 (in), 100 VCCO (power), 101 GND (power), 102 CLK3/IN4 (in), 111 GND (power), 120 VCCO (power), 121 GND (power), 130 GND (power), 139 JTAGEN (in), 140 VCC (power), 141 GND (power), 142 VCCO (power), 151 GND (power), 160 VCCO (power)

## CY37128P160-100AI
designator U?
Ultra37000 5V, ISR High-Performance CPLD
footprint A160_N (Thin QFP, 160-Leads, Body 24x24mm, Pitch 0.5mm, IPC Medium Density)
footprint A160_L (Thin QFP, 160-Leads, Body 24x24mm, Pitch 0.5mm, IPC High Density)
footprint A160_M (Thin QFP, 160-Leads, Body 24x24mm, Pitch 0.5mm, IPC Low Density)
3D model CY37128P160-A160 (160-Pin Thin Quad Flat Pack 0.5 mm Pitch)
part A pins: 2 I/O16 (io), 3 I/O17 (io), 4 I/O18 (io), 5 I/O19 (io), 6 I/O20/TCK (io), 7 I/O21 (io), 8 I/O22 (io), 9 I/O23 (io), 11 I/O24 (io), 12 I/O25 (io), 13 I/O26 (io), 14 I/O27 (io), 15 I/O28 (io), 16 I/O29 (io), 17 I/O30 (io), 18 I/O31 (io), 23 I/O32 (io), 24 I/O33 (io), 25 I/O34 (io), 26 I/O35 (io), 27 I/O36 (io), 28 I/O37 (io), 29 I/O38 (io), 30 I/O39 (io), 32 I/O40 (io), 33 I/O41 (io), 34 I/O42 (io), 35 I/O43 (io), 36 I/O44 (io), 37 I/O45 (io), 38 I/O46 (io), 39 I/O47 (io), 42 I/O48 (io), 43 I/O49 (io), 44 I/O50 (io), 45 I/O51 (io), 46 I/O52/TMS (io), 47 I/O53 (io), 48 I/O54 (io), 49 I/O55 (io), 51 I/O56 (io), 52 I/O57 (io), 53 I/O58 (io), 54 I/O59 (io), 55 I/O60 (io), 56 I/O61 (io), 57 I/O62 (io), 58 I/O63 (io), 63 I/O64 (io), 64 I/O65 (io), 65 I/O66 (io), 66 I/O67 (io), 67 I/O68 (io), 68 I/O69 (io), 69 I/O70 (io), 70 I/O71 (io), 72 I/O72 (io), 73 I/O73 (io), 74 I/O74 (io), 75 I/O75 (io), 76 I/O76/TDO (io), 77 I/O77 (io), 78 I/O78 (io), 79 I/O79 (io), 82 I/O80 (io), 83 I/O81 (io), 84 I/O82 (io), 85 I/O83 (io), 86 I/O84 (io), 87 I/O85 (io), 88 I/O86 (io), 89 I/O87 (io), 91 I/O88 (io), 92 I/O89 (io), 93 I/O90 (io), 94 I/O91 (io), 95 I/O92 (io), 96 I/O93 (io), 97 I/O94 (io), 98 I/O95 (io), 103 I/O96 (io), 104 I/O97 (io), 105 I/O98 (io), 106 I/O99 (io), 107 I/O100 (io), 108 I/O101 (io), 109 I/O102 (io), 110 I/O103 (io), 112 I/O104 (io), 113 I/O105 (io), 114 I/O106 (io), 115 I/O107 (io), 116 I/O108/TDI (io), 117 I/O109 (io), 118 I/O110 (io), 119 I/O111 (io), 122 I/O112 (io), 123 I/O113 (io), 124 I/O114 (io), 125 I/O115 (io), 126 I/O116 (io), 127 I/O117 (io), 128 I/O118 (io), 129 I/O119 (io), 131 I/O120 (io), 132 I/O121 (io), 133 I/O122 (io), 134 I/O123 (io), 135 I/O124 (io), 136 I/O125 (io), 137 I/O126 (io), 138 I/O127 (io), 143 I/O0 (io), 144 I/O1 (io), 145 I/O2 (io), 146 I/O3 (io), 147 I/O4 (io), 148 I/O5 (io), 149 I/O6 (io), 150 I/O7 (io), 152 I/O8 (io), 153 I/O9 (io), 154 I/O10 (io), 155 I/O11 (io), 156 I/O12 (io), 157 I/O13 (io), 158 I/O14 (io), 159 I/O15 (io)
part B pins: 1 GND (power), 10 GND (power), 19 CLK0/IN0 (in), 20 VCCO (power), 21 GND (power), 22 CLK1/IN1 (in), 31 GND (power), 40 VCCO (power), 41 GND (power), 50 GND (power), 59 IN2 (in), 60 VCCO (power), 61 GND (power), 62 VCC (power), 71 GND (power), 80 VCCO (power), 81 GND (power), 90 GND (power), 99 CLK2/IN3 (in), 100 VCCO (power), 101 GND (power), 102 CLK3/IN4 (in), 111 GND (power), 120 VCCO (power), 121 GND (power), 130 GND (power), 139 JTAGEN (in), 140 VCC (power), 141 GND (power), 142 VCCO (power), 151 GND (power), 160 VCCO (power)

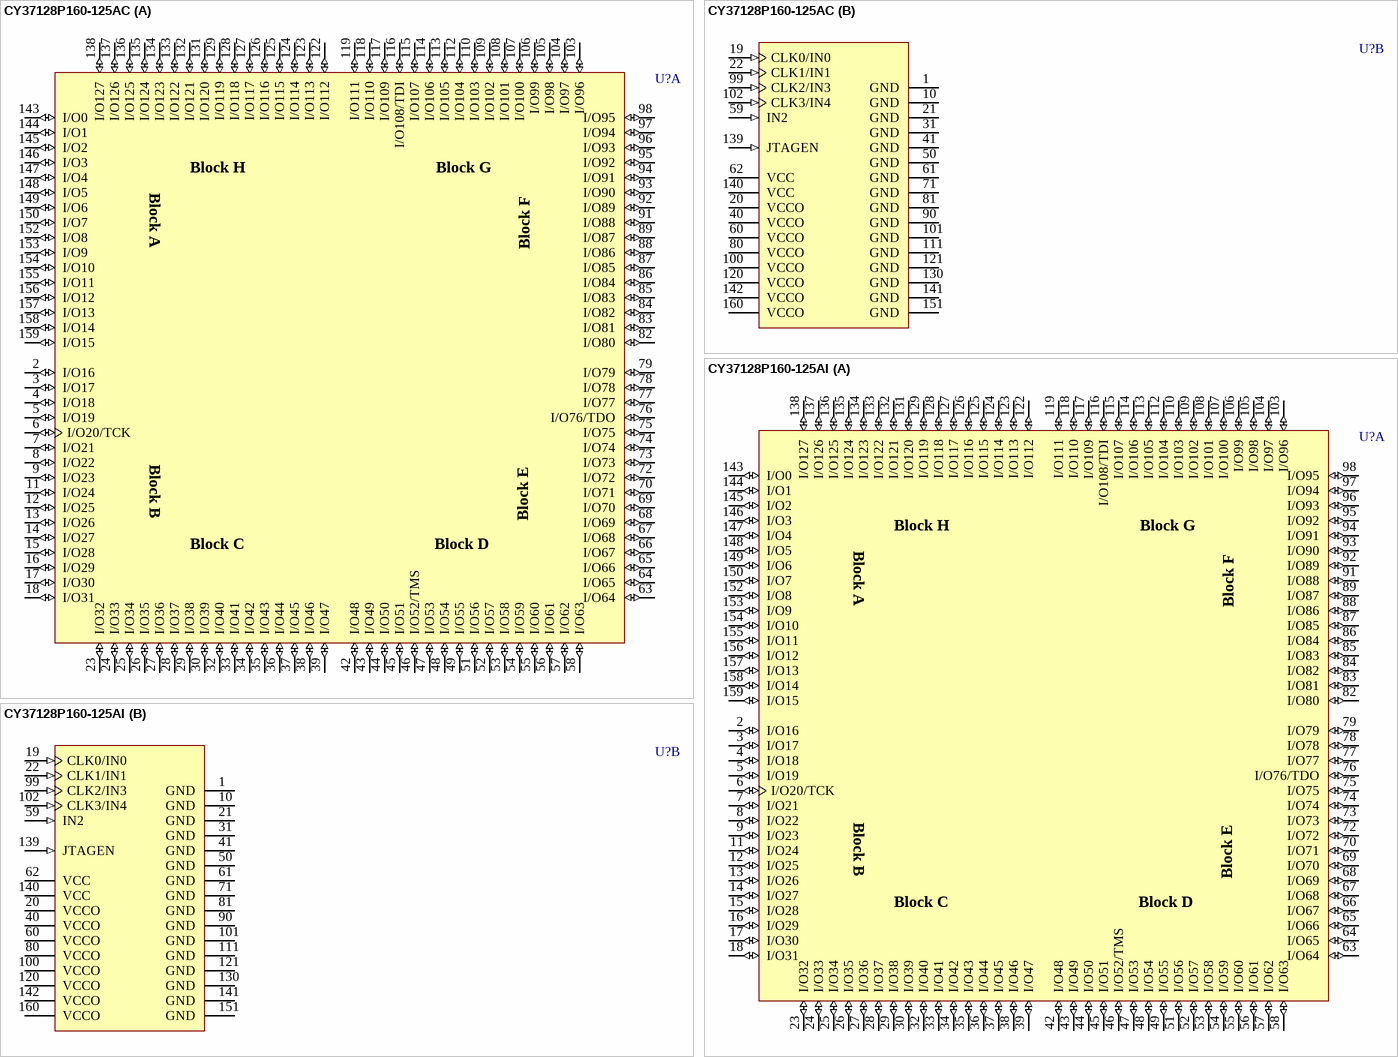
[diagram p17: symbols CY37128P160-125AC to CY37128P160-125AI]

## CY37128P160-125AC
designator U?
Ultra37000 5V, ISR High-Performance CPLD
footprint A160_N (Thin QFP, 160-Leads, Body 24x24mm, Pitch 0.5mm, IPC Medium Density)
footprint A160_L (Thin QFP, 160-Leads, Body 24x24mm, Pitch 0.5mm, IPC High Density)
footprint A160_M (Thin QFP, 160-Leads, Body 24x24mm, Pitch 0.5mm, IPC Low Density)
3D model CY37128P160-A160 (160-Pin Thin Quad Flat Pack 0.5 mm Pitch)
part A pins: 2 I/O16 (io), 3 I/O17 (io), 4 I/O18 (io), 5 I/O19 (io), 6 I/O20/TCK (io), 7 I/O21 (io), 8 I/O22 (io), 9 I/O23 (io), 11 I/O24 (io), 12 I/O25 (io), 13 I/O26 (io), 14 I/O27 (io), 15 I/O28 (io), 16 I/O29 (io), 17 I/O30 (io), 18 I/O31 (io), 23 I/O32 (io), 24 I/O33 (io), 25 I/O34 (io), 26 I/O35 (io), 27 I/O36 (io), 28 I/O37 (io), 29 I/O38 (io), 30 I/O39 (io), 32 I/O40 (io), 33 I/O41 (io), 34 I/O42 (io), 35 I/O43 (io), 36 I/O44 (io), 37 I/O45 (io), 38 I/O46 (io), 39 I/O47 (io), 42 I/O48 (io), 43 I/O49 (io), 44 I/O50 (io), 45 I/O51 (io), 46 I/O52/TMS (io), 47 I/O53 (io), 48 I/O54 (io), 49 I/O55 (io), 51 I/O56 (io), 52 I/O57 (io), 53 I/O58 (io), 54 I/O59 (io), 55 I/O60 (io), 56 I/O61 (io), 57 I/O62 (io), 58 I/O63 (io), 63 I/O64 (io), 64 I/O65 (io), 65 I/O66 (io), 66 I/O67 (io), 67 I/O68 (io), 68 I/O69 (io), 69 I/O70 (io), 70 I/O71 (io), 72 I/O72 (io), 73 I/O73 (io), 74 I/O74 (io), 75 I/O75 (io), 76 I/O76/TDO (io), 77 I/O77 (io), 78 I/O78 (io), 79 I/O79 (io), 82 I/O80 (io), 83 I/O81 (io), 84 I/O82 (io), 85 I/O83 (io), 86 I/O84 (io), 87 I/O85 (io), 88 I/O86 (io), 89 I/O87 (io), 91 I/O88 (io), 92 I/O89 (io), 93 I/O90 (io), 94 I/O91 (io), 95 I/O92 (io), 96 I/O93 (io), 97 I/O94 (io), 98 I/O95 (io), 103 I/O96 (io), 104 I/O97 (io), 105 I/O98 (io), 106 I/O99 (io), 107 I/O100 (io), 108 I/O101 (io), 109 I/O102 (io), 110 I/O103 (io), 112 I/O104 (io), 113 I/O105 (io), 114 I/O106 (io), 115 I/O107 (io), 116 I/O108/TDI (io), 117 I/O109 (io), 118 I/O110 (io), 119 I/O111 (io), 122 I/O112 (io), 123 I/O113 (io), 124 I/O114 (io), 125 I/O115 (io), 126 I/O116 (io), 127 I/O117 (io), 128 I/O118 (io), 129 I/O119 (io), 131 I/O120 (io), 132 I/O121 (io), 133 I/O122 (io), 134 I/O123 (io), 135 I/O124 (io), 136 I/O125 (io), 137 I/O126 (io), 138 I/O127 (io), 143 I/O0 (io), 144 I/O1 (io), 145 I/O2 (io), 146 I/O3 (io), 147 I/O4 (io), 148 I/O5 (io), 149 I/O6 (io), 150 I/O7 (io), 152 I/O8 (io), 153 I/O9 (io), 154 I/O10 (io), 155 I/O11 (io), 156 I/O12 (io), 157 I/O13 (io), 158 I/O14 (io), 159 I/O15 (io)
part B pins: 1 GND (power), 10 GND (power), 19 CLK0/IN0 (in), 20 VCCO (power), 21 GND (power), 22 CLK1/IN1 (in), 31 GND (power), 40 VCCO (power), 41 GND (power), 50 GND (power), 59 IN2 (in), 60 VCCO (power), 61 GND (power), 62 VCC (power), 71 GND (power), 80 VCCO (power), 81 GND (power), 90 GND (power), 99 CLK2/IN3 (in), 100 VCCO (power), 101 GND (power), 102 CLK3/IN4 (in), 111 GND (power), 120 VCCO (power), 121 GND (power), 130 GND (power), 139 JTAGEN (in), 140 VCC (power), 141 GND (power), 142 VCCO (power), 151 GND (power), 160 VCCO (power)

## CY37128P160-125AI
designator U?
Ultra37000 5V, ISR High-Performance CPLD
footprint A160_N (Thin QFP, 160-Leads, Body 24x24mm, Pitch 0.5mm, IPC Medium Density)
footprint A160_L (Thin QFP, 160-Leads, Body 24x24mm, Pitch 0.5mm, IPC High Density)
footprint A160_M (Thin QFP, 160-Leads, Body 24x24mm, Pitch 0.5mm, IPC Low Density)
3D model CY37128P160-A160 (160-Pin Thin Quad Flat Pack 0.5 mm Pitch)
part A pins: 2 I/O16 (io), 3 I/O17 (io), 4 I/O18 (io), 5 I/O19 (io), 6 I/O20/TCK (io), 7 I/O21 (io), 8 I/O22 (io), 9 I/O23 (io), 11 I/O24 (io), 12 I/O25 (io), 13 I/O26 (io), 14 I/O27 (io), 15 I/O28 (io), 16 I/O29 (io), 17 I/O30 (io), 18 I/O31 (io), 23 I/O32 (io), 24 I/O33 (io), 25 I/O34 (io), 26 I/O35 (io), 27 I/O36 (io), 28 I/O37 (io), 29 I/O38 (io), 30 I/O39 (io), 32 I/O40 (io), 33 I/O41 (io), 34 I/O42 (io), 35 I/O43 (io), 36 I/O44 (io), 37 I/O45 (io), 38 I/O46 (io), 39 I/O47 (io), 42 I/O48 (io), 43 I/O49 (io), 44 I/O50 (io), 45 I/O51 (io), 46 I/O52/TMS (io), 47 I/O53 (io), 48 I/O54 (io), 49 I/O55 (io), 51 I/O56 (io), 52 I/O57 (io), 53 I/O58 (io), 54 I/O59 (io), 55 I/O60 (io), 56 I/O61 (io), 57 I/O62 (io), 58 I/O63 (io), 63 I/O64 (io), 64 I/O65 (io), 65 I/O66 (io), 66 I/O67 (io), 67 I/O68 (io), 68 I/O69 (io), 69 I/O70 (io), 70 I/O71 (io), 72 I/O72 (io), 73 I/O73 (io), 74 I/O74 (io), 75 I/O75 (io), 76 I/O76/TDO (io), 77 I/O77 (io), 78 I/O78 (io), 79 I/O79 (io), 82 I/O80 (io), 83 I/O81 (io), 84 I/O82 (io), 85 I/O83 (io), 86 I/O84 (io), 87 I/O85 (io), 88 I/O86 (io), 89 I/O87 (io), 91 I/O88 (io), 92 I/O89 (io), 93 I/O90 (io), 94 I/O91 (io), 95 I/O92 (io), 96 I/O93 (io), 97 I/O94 (io), 98 I/O95 (io), 103 I/O96 (io), 104 I/O97 (io), 105 I/O98 (io), 106 I/O99 (io), 107 I/O100 (io), 108 I/O101 (io), 109 I/O102 (io), 110 I/O103 (io), 112 I/O104 (io), 113 I/O105 (io), 114 I/O106 (io), 115 I/O107 (io), 116 I/O108/TDI (io), 117 I/O109 (io), 118 I/O110 (io), 119 I/O111 (io), 122 I/O112 (io), 123 I/O113 (io), 124 I/O114 (io), 125 I/O115 (io), 126 I/O116 (io), 127 I/O117 (io), 128 I/O118 (io), 129 I/O119 (io), 131 I/O120 (io), 132 I/O121 (io), 133 I/O122 (io), 134 I/O123 (io), 135 I/O124 (io), 136 I/O125 (io), 137 I/O126 (io), 138 I/O127 (io), 143 I/O0 (io), 144 I/O1 (io), 145 I/O2 (io), 146 I/O3 (io), 147 I/O4 (io), 148 I/O5 (io), 149 I/O6 (io), 150 I/O7 (io), 152 I/O8 (io), 153 I/O9 (io), 154 I/O10 (io), 155 I/O11 (io), 156 I/O12 (io), 157 I/O13 (io), 158 I/O14 (io), 159 I/O15 (io)
part B pins: 1 GND (power), 10 GND (power), 19 CLK0/IN0 (in), 20 VCCO (power), 21 GND (power), 22 CLK1/IN1 (in), 31 GND (power), 40 VCCO (power), 41 GND (power), 50 GND (power), 59 IN2 (in), 60 VCCO (power), 61 GND (power), 62 VCC (power), 71 GND (power), 80 VCCO (power), 81 GND (power), 90 GND (power), 99 CLK2/IN3 (in), 100 VCCO (power), 101 GND (power), 102 CLK3/IN4 (in), 111 GND (power), 120 VCCO (power), 121 GND (power), 130 GND (power), 139 JTAGEN (in), 140 VCC (power), 141 GND (power), 142 VCCO (power), 151 GND (power), 160 VCCO (power)

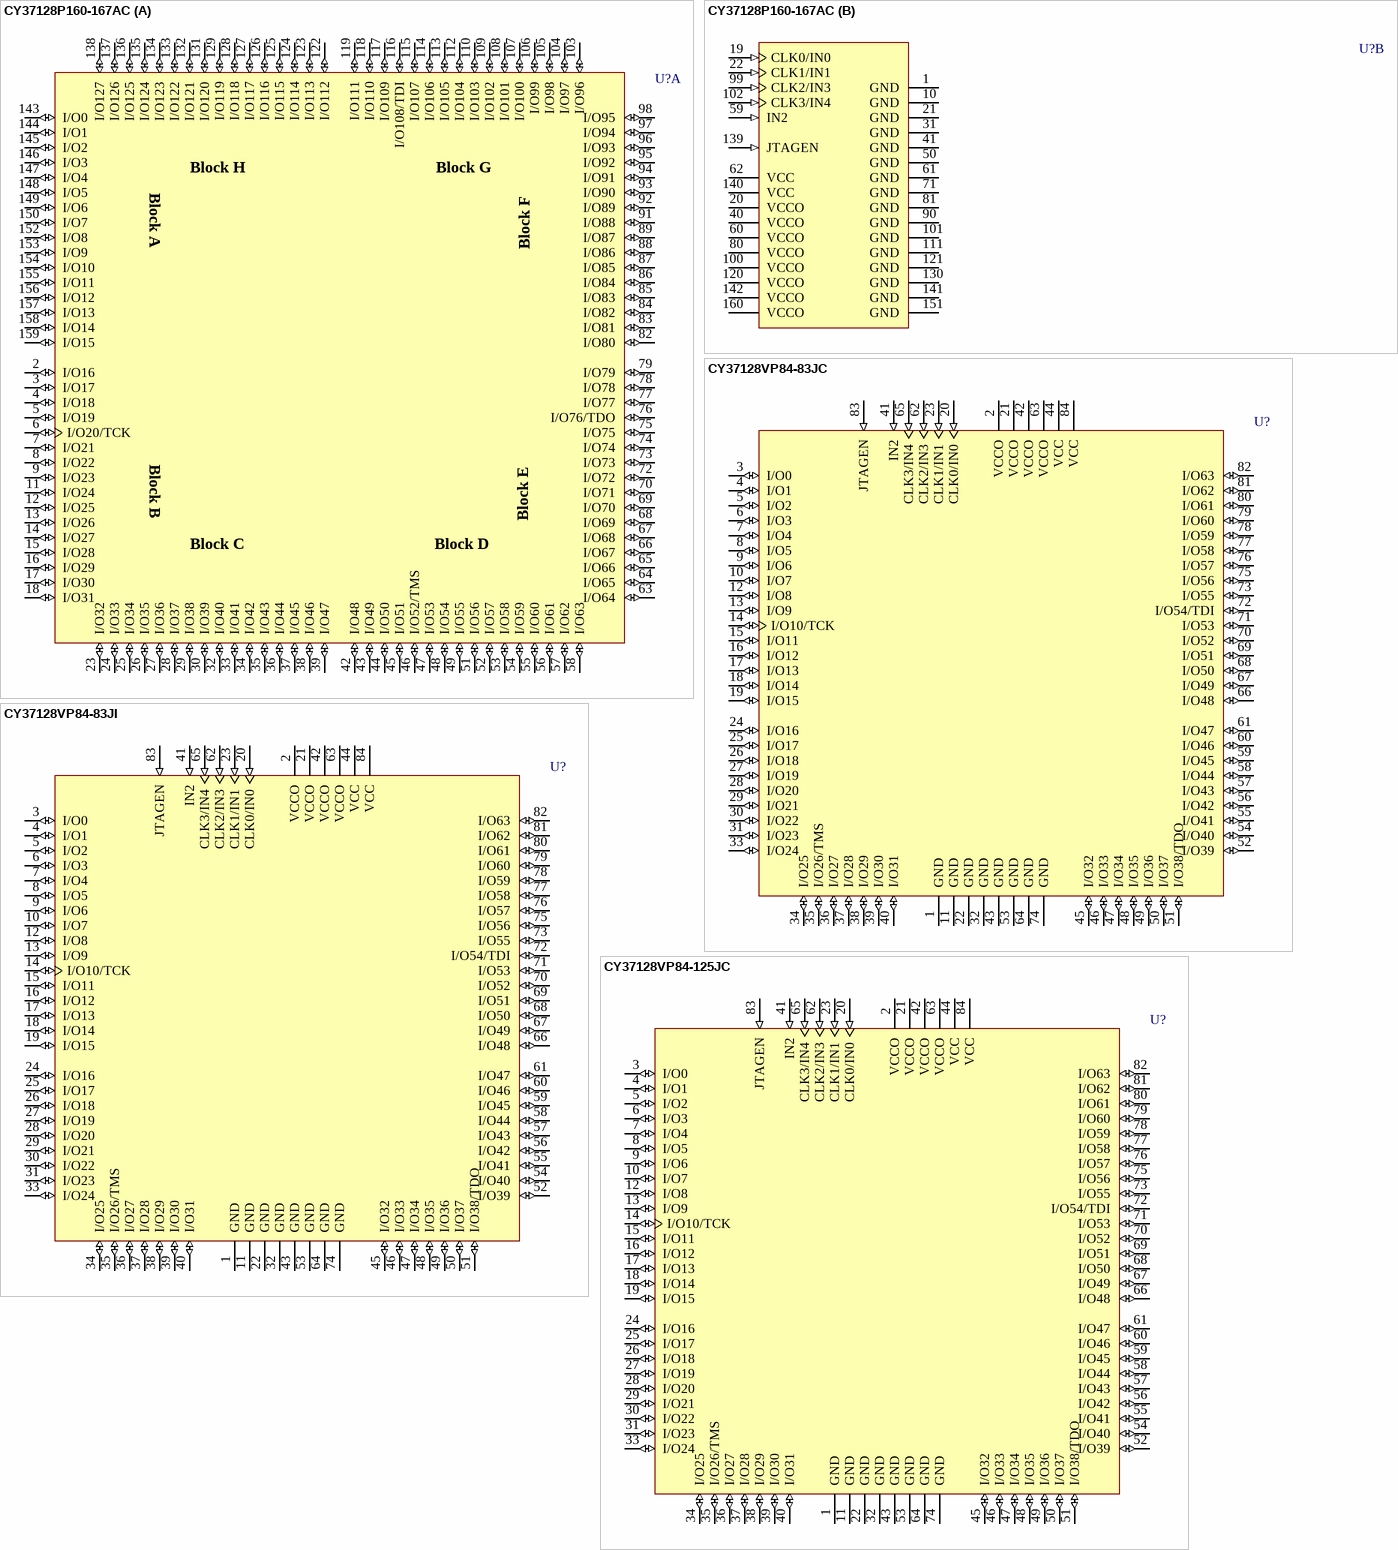
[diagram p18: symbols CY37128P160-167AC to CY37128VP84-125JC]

## CY37128P160-167AC
designator U?
Ultra37000 5V, ISR High-Performance CPLD
footprint A160_N (Thin QFP, 160-Leads, Body 24x24mm, Pitch 0.5mm, IPC Medium Density)
footprint A160_L (Thin QFP, 160-Leads, Body 24x24mm, Pitch 0.5mm, IPC High Density)
footprint A160_M (Thin QFP, 160-Leads, Body 24x24mm, Pitch 0.5mm, IPC Low Density)
3D model CY37128P160-A160 (160-Pin Thin Quad Flat Pack 0.5 mm Pitch)
part A pins: 2 I/O16 (io), 3 I/O17 (io), 4 I/O18 (io), 5 I/O19 (io), 6 I/O20/TCK (io), 7 I/O21 (io), 8 I/O22 (io), 9 I/O23 (io), 11 I/O24 (io), 12 I/O25 (io), 13 I/O26 (io), 14 I/O27 (io), 15 I/O28 (io), 16 I/O29 (io), 17 I/O30 (io), 18 I/O31 (io), 23 I/O32 (io), 24 I/O33 (io), 25 I/O34 (io), 26 I/O35 (io), 27 I/O36 (io), 28 I/O37 (io), 29 I/O38 (io), 30 I/O39 (io), 32 I/O40 (io), 33 I/O41 (io), 34 I/O42 (io), 35 I/O43 (io), 36 I/O44 (io), 37 I/O45 (io), 38 I/O46 (io), 39 I/O47 (io), 42 I/O48 (io), 43 I/O49 (io), 44 I/O50 (io), 45 I/O51 (io), 46 I/O52/TMS (io), 47 I/O53 (io), 48 I/O54 (io), 49 I/O55 (io), 51 I/O56 (io), 52 I/O57 (io), 53 I/O58 (io), 54 I/O59 (io), 55 I/O60 (io), 56 I/O61 (io), 57 I/O62 (io), 58 I/O63 (io), 63 I/O64 (io), 64 I/O65 (io), 65 I/O66 (io), 66 I/O67 (io), 67 I/O68 (io), 68 I/O69 (io), 69 I/O70 (io), 70 I/O71 (io), 72 I/O72 (io), 73 I/O73 (io), 74 I/O74 (io), 75 I/O75 (io), 76 I/O76/TDO (io), 77 I/O77 (io), 78 I/O78 (io), 79 I/O79 (io), 82 I/O80 (io), 83 I/O81 (io), 84 I/O82 (io), 85 I/O83 (io), 86 I/O84 (io), 87 I/O85 (io), 88 I/O86 (io), 89 I/O87 (io), 91 I/O88 (io), 92 I/O89 (io), 93 I/O90 (io), 94 I/O91 (io), 95 I/O92 (io), 96 I/O93 (io), 97 I/O94 (io), 98 I/O95 (io), 103 I/O96 (io), 104 I/O97 (io), 105 I/O98 (io), 106 I/O99 (io), 107 I/O100 (io), 108 I/O101 (io), 109 I/O102 (io), 110 I/O103 (io), 112 I/O104 (io), 113 I/O105 (io), 114 I/O106 (io), 115 I/O107 (io), 116 I/O108/TDI (io), 117 I/O109 (io), 118 I/O110 (io), 119 I/O111 (io), 122 I/O112 (io), 123 I/O113 (io), 124 I/O114 (io), 125 I/O115 (io), 126 I/O116 (io), 127 I/O117 (io), 128 I/O118 (io), 129 I/O119 (io), 131 I/O120 (io), 132 I/O121 (io), 133 I/O122 (io), 134 I/O123 (io), 135 I/O124 (io), 136 I/O125 (io), 137 I/O126 (io), 138 I/O127 (io), 143 I/O0 (io), 144 I/O1 (io), 145 I/O2 (io), 146 I/O3 (io), 147 I/O4 (io), 148 I/O5 (io), 149 I/O6 (io), 150 I/O7 (io), 152 I/O8 (io), 153 I/O9 (io), 154 I/O10 (io), 155 I/O11 (io), 156 I/O12 (io), 157 I/O13 (io), 158 I/O14 (io), 159 I/O15 (io)
part B pins: 1 GND (power), 10 GND (power), 19 CLK0/IN0 (in), 20 VCCO (power), 21 GND (power), 22 CLK1/IN1 (in), 31 GND (power), 40 VCCO (power), 41 GND (power), 50 GND (power), 59 IN2 (in), 60 VCCO (power), 61 GND (power), 62 VCC (power), 71 GND (power), 80 VCCO (power), 81 GND (power), 90 GND (power), 99 CLK2/IN3 (in), 100 VCCO (power), 101 GND (power), 102 CLK3/IN4 (in), 111 GND (power), 120 VCCO (power), 121 GND (power), 130 GND (power), 139 JTAGEN (in), 140 VCC (power), 141 GND (power), 142 VCCO (power), 151 GND (power), 160 VCCO (power)

## CY37128VP84-83JC
designator U?
Ultra37000 3.3V, ISR High-Performance CPLD; ComponentAvailability: Obsolete
footprint J83_N (Leaded Chip Carrier, 84-Leads, Body 29.3x29.3mm, Pitch 1.27mm, IPC Medium Density)
footprint J83_L (Leaded Chip Carrier, 84-Leads, Body 29.3x29.3mm, Pitch 1.27mm, IPC High Density)
footprint J83_M (Leaded Chip Carrier, 84-Leads, Body 29.3x29.3mm, Pitch 1.27mm, IPC Low Density)
3D model CY37128VP84-J83 (84-Pin Plastic Leaded Chip Carrier 1.27 mm Pitch)
pins: 1 GND (power), 2 VCCO (power), 3 I/O0 (io), 4 I/O1 (io), 5 I/O2 (io), 6 I/O3 (io), 7 I/O4 (io), 8 I/O5 (io), 9 I/O6 (io), 10 I/O7 (io), 11 GND (power), 12 I/O8 (io), 13 I/O9 (io), 14 I/O10/TCK (io), 15 I/O11 (io), 16 I/O12 (io), 17 I/O13 (io), 18 I/O14 (io), 19 I/O15 (io), 20 CLK0/IN0 (in), 21 VCCO (power), 22 GND (power), 23 CLK1/IN1 (in), 24 I/O16 (io), 25 I/O17 (io), 26 I/O18 (io), 27 I/O19 (io), 28 I/O20 (io), 29 I/O21 (io), 30 I/O22 (io), 31 I/O23 (io), 32 GND (power), 33 I/O24 (io), 34 I/O25 (io), 35 I/O26/TMS (io), 36 I/O27 (io), 37 I/O28 (io), 38 I/O29 (io), 39 I/O30 (io), 40 I/O31 (io), 41 IN2 (in), 42 VCCO (power), 43 GND (power), 44 VCC (power), 45 I/O32 (io), 46 I/O33 (io), 47 I/O34 (io), 48 I/O35 (io), 49 I/O36 (io), 50 I/O37 (io), 51 I/O38/TDO (io), 52 I/O39 (io), 53 GND (power), 54 I/O40 (io), 55 I/O41 (io), 56 I/O42 (io), 57 I/O43 (io), 58 I/O44 (io), 59 I/O45 (io), 60 I/O46 (io), 61 I/O47 (io), 62 CLK2/IN3 (in), 63 VCCO (power), 64 GND (power), 65 CLK3/IN4 (in), 66 I/O48 (io), 67 I/O49 (io), 68 I/O50 (io), 69 I/O51 (io), 70 I/O52 (io), 71 I/O53 (io), 72 I/O54/TDI (io), 73 I/O55 (io), 74 GND (power), 75 I/O56 (io), 76 I/O57 (io), 77 I/O58 (io), 78 I/O59 (io), 79 I/O60 (io), 80 I/O61 (io), 81 I/O62 (io), 82 I/O63 (io), 83 JTAGEN (in), 84 VCC (power)

## CY37128VP84-83JI
designator U?
Ultra37000 3.3V, ISR High-Performance CPLD; ComponentAvailability: Obsolete
footprint J83_N (Leaded Chip Carrier, 84-Leads, Body 29.3x29.3mm, Pitch 1.27mm, IPC Medium Density)
footprint J83_L (Leaded Chip Carrier, 84-Leads, Body 29.3x29.3mm, Pitch 1.27mm, IPC High Density)
footprint J83_M (Leaded Chip Carrier, 84-Leads, Body 29.3x29.3mm, Pitch 1.27mm, IPC Low Density)
3D model CY37128VP84-J83 (84-Pin Plastic Leaded Chip Carrier 1.27 mm Pitch)
pins: 1 GND (power), 2 VCCO (power), 3 I/O0 (io), 4 I/O1 (io), 5 I/O2 (io), 6 I/O3 (io), 7 I/O4 (io), 8 I/O5 (io), 9 I/O6 (io), 10 I/O7 (io), 11 GND (power), 12 I/O8 (io), 13 I/O9 (io), 14 I/O10/TCK (io), 15 I/O11 (io), 16 I/O12 (io), 17 I/O13 (io), 18 I/O14 (io), 19 I/O15 (io), 20 CLK0/IN0 (in), 21 VCCO (power), 22 GND (power), 23 CLK1/IN1 (in), 24 I/O16 (io), 25 I/O17 (io), 26 I/O18 (io), 27 I/O19 (io), 28 I/O20 (io), 29 I/O21 (io), 30 I/O22 (io), 31 I/O23 (io), 32 GND (power), 33 I/O24 (io), 34 I/O25 (io), 35 I/O26/TMS (io), 36 I/O27 (io), 37 I/O28 (io), 38 I/O29 (io), 39 I/O30 (io), 40 I/O31 (io), 41 IN2 (in), 42 VCCO (power), 43 GND (power), 44 VCC (power), 45 I/O32 (io), 46 I/O33 (io), 47 I/O34 (io), 48 I/O35 (io), 49 I/O36 (io), 50 I/O37 (io), 51 I/O38/TDO (io), 52 I/O39 (io), 53 GND (power), 54 I/O40 (io), 55 I/O41 (io), 56 I/O42 (io), 57 I/O43 (io), 58 I/O44 (io), 59 I/O45 (io), 60 I/O46 (io), 61 I/O47 (io), 62 CLK2/IN3 (in), 63 VCCO (power), 64 GND (power), 65 CLK3/IN4 (in), 66 I/O48 (io), 67 I/O49 (io), 68 I/O50 (io), 69 I/O51 (io), 70 I/O52 (io), 71 I/O53 (io), 72 I/O54/TDI (io), 73 I/O55 (io), 74 GND (power), 75 I/O56 (io), 76 I/O57 (io), 77 I/O58 (io), 78 I/O59 (io), 79 I/O60 (io), 80 I/O61 (io), 81 I/O62 (io), 82 I/O63 (io), 83 JTAGEN (in), 84 VCC (power)

## CY37128VP84-125JC
designator U?
Ultra37000 3.3V, ISR High-Performance CPLD; ComponentAvailability: Obsolete
footprint J83_N (Leaded Chip Carrier, 84-Leads, Body 29.3x29.3mm, Pitch 1.27mm, IPC Medium Density)
footprint J83_L (Leaded Chip Carrier, 84-Leads, Body 29.3x29.3mm, Pitch 1.27mm, IPC High Density)
footprint J83_M (Leaded Chip Carrier, 84-Leads, Body 29.3x29.3mm, Pitch 1.27mm, IPC Low Density)
3D model CY37128VP84-J83 (84-Pin Plastic Leaded Chip Carrier 1.27 mm Pitch)
pins: 1 GND (power), 2 VCCO (power), 3 I/O0 (io), 4 I/O1 (io), 5 I/O2 (io), 6 I/O3 (io), 7 I/O4 (io), 8 I/O5 (io), 9 I/O6 (io), 10 I/O7 (io), 11 GND (power), 12 I/O8 (io), 13 I/O9 (io), 14 I/O10/TCK (io), 15 I/O11 (io), 16 I/O12 (io), 17 I/O13 (io), 18 I/O14 (io), 19 I/O15 (io), 20 CLK0/IN0 (in), 21 VCCO (power), 22 GND (power), 23 CLK1/IN1 (in), 24 I/O16 (io), 25 I/O17 (io), 26 I/O18 (io), 27 I/O19 (io), 28 I/O20 (io), 29 I/O21 (io), 30 I/O22 (io), 31 I/O23 (io), 32 GND (power), 33 I/O24 (io), 34 I/O25 (io), 35 I/O26/TMS (io), 36 I/O27 (io), 37 I/O28 (io), 38 I/O29 (io), 39 I/O30 (io), 40 I/O31 (io), 41 IN2 (in), 42 VCCO (power), 43 GND (power), 44 VCC (power), 45 I/O32 (io), 46 I/O33 (io), 47 I/O34 (io), 48 I/O35 (io), 49 I/O36 (io), 50 I/O37 (io), 51 I/O38/TDO (io), 52 I/O39 (io), 53 GND (power), 54 I/O40 (io), 55 I/O41 (io), 56 I/O42 (io), 57 I/O43 (io), 58 I/O44 (io), 59 I/O45 (io), 60 I/O46 (io), 61 I/O47 (io), 62 CLK2/IN3 (in), 63 VCCO (power), 64 GND (power), 65 CLK3/IN4 (in), 66 I/O48 (io), 67 I/O49 (io), 68 I/O50 (io), 69 I/O51 (io), 70 I/O52 (io), 71 I/O53 (io), 72 I/O54/TDI (io), 73 I/O55 (io), 74 GND (power), 75 I/O56 (io), 76 I/O57 (io), 77 I/O58 (io), 78 I/O59 (io), 79 I/O60 (io), 80 I/O61 (io), 81 I/O62 (io), 82 I/O63 (io), 83 JTAGEN (in), 84 VCC (power)

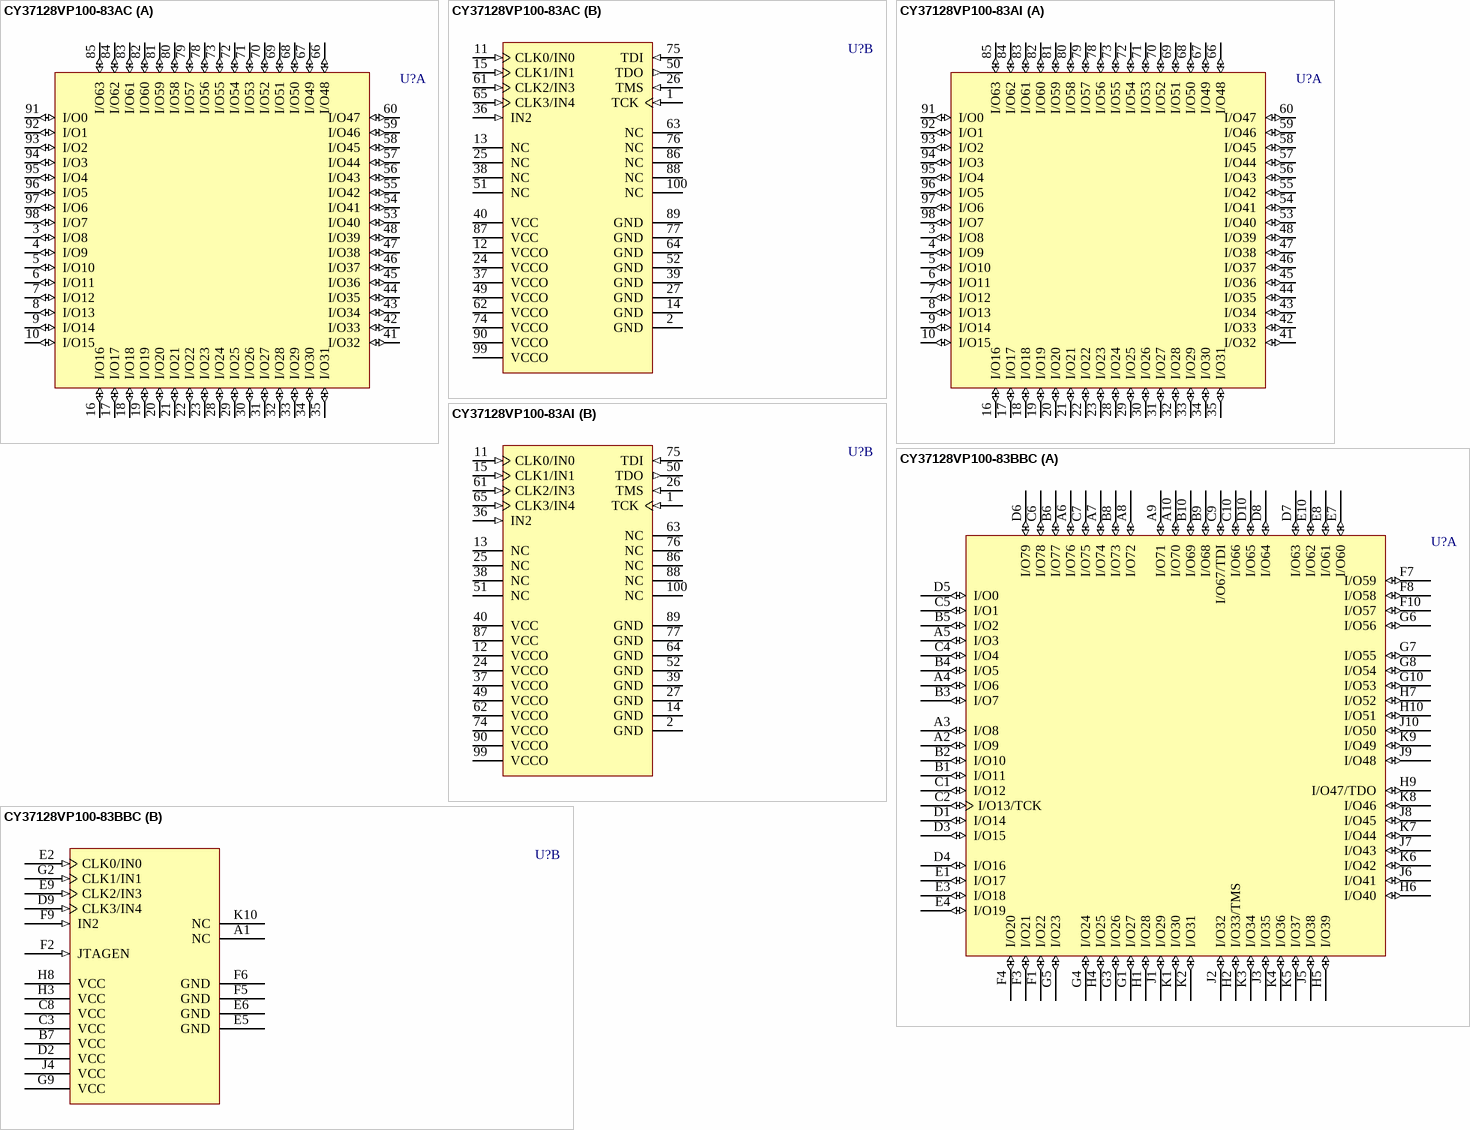
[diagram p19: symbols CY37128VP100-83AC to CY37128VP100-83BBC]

## CY37128VP100-83AC
designator U?
Ultra37000 3.3V, ISR High-Performance CPLD
footprint A100_N (Thin QFP, 100-Leads, Body 14x14mm, Pitch 0.5mm, IPC Medium Density)
footprint A100_L (Thin QFP, 100-Leads, Body 14x14mm, Pitch 0.5mm, IPC High Density)
footprint A100_M (Thin QFP, 100-Leads, Body 14x14mm, Pitch 0.5mm, IPC Low Density)
3D model CY37128VP100-A100 (100-Pin Thin Quad Flat Pack 0.5 mm Pitch)
part A pins: 3 I/O8 (io), 4 I/O9 (io), 5 I/O10 (io), 6 I/O11 (io), 7 I/O12 (io), 8 I/O13 (io), 9 I/O14 (io), 10 I/O15 (io), 16 I/O16 (io), 17 I/O17 (io), 18 I/O18 (io), 19 I/O19 (io), 20 I/O20 (io), 21 I/O21 (io), 22 I/O22 (io), 23 I/O23 (io), 28 I/O24 (io), 29 I/O25 (io), 30 I/O26 (io), 31 I/O27 (io), 32 I/O28 (io), 33 I/O29 (io), 34 I/O30 (io), 35 I/O31 (io), 41 I/O32 (io), 42 I/O33 (io), 43 I/O34 (io), 44 I/O35 (io), 45 I/O36 (io), 46 I/O37 (io), 47 I/O38 (io), 48 I/O39 (io), 53 I/O40 (io), 54 I/O41 (io), 55 I/O42 (io), 56 I/O43 (io), 57 I/O44 (io), 58 I/O45 (io), 59 I/O46 (io), 60 I/O47 (io), 66 I/O48 (io), 67 I/O49 (io), 68 I/O50 (io), 69 I/O51 (io), 70 I/O52 (io), 71 I/O53 (io), 72 I/O54 (io), 73 I/O55 (io), 78 I/O56 (io), 79 I/O57 (io), 80 I/O58 (io), 81 I/O59 (io), 82 I/O60 (io), 83 I/O61 (io), 84 I/O62 (io), 85 I/O63 (io), 91 I/O0 (io), 92 I/O1 (io), 93 I/O2 (io), 94 I/O3 (io), 95 I/O4 (io), 96 I/O5 (io), 97 I/O6 (io), 98 I/O7 (io)
part B pins: 1 TCK (in), 2 GND (power), 11 CLK0/IN0 (in), 12 VCCO (power), 13 NC, 14 GND (power), 15 CLK1/IN1 (in), 24 VCCO (power), 25 NC, 26 TMS (in), 27 GND (power), 36 IN2 (in), 37 VCCO (power), 38 NC, 39 GND (power), 40 VCC (power), 49 VCCO (power), 50 TDO (out), 51 NC, 52 GND (power), 61 CLK2/IN3 (in), 62 VCCO (power), 63 NC, 64 GND (power), 65 CLK3/IN4 (in), 74 VCCO (power), 75 TDI (in), 76 NC, 77 GND (power), 86 NC, 87 VCC (power), 88 NC, 89 GND (power), 90 VCCO (power), 99 VCCO (power), 100 NC

## CY37128VP100-83AI
designator U?
Ultra37000 3.3V, ISR High-Performance CPLD
footprint A100_N (Thin QFP, 100-Leads, Body 14x14mm, Pitch 0.5mm, IPC Medium Density)
footprint A100_L (Thin QFP, 100-Leads, Body 14x14mm, Pitch 0.5mm, IPC High Density)
footprint A100_M (Thin QFP, 100-Leads, Body 14x14mm, Pitch 0.5mm, IPC Low Density)
3D model CY37128VP100-A100 (100-Pin Thin Quad Flat Pack 0.5 mm Pitch)
part A pins: 3 I/O8 (io), 4 I/O9 (io), 5 I/O10 (io), 6 I/O11 (io), 7 I/O12 (io), 8 I/O13 (io), 9 I/O14 (io), 10 I/O15 (io), 16 I/O16 (io), 17 I/O17 (io), 18 I/O18 (io), 19 I/O19 (io), 20 I/O20 (io), 21 I/O21 (io), 22 I/O22 (io), 23 I/O23 (io), 28 I/O24 (io), 29 I/O25 (io), 30 I/O26 (io), 31 I/O27 (io), 32 I/O28 (io), 33 I/O29 (io), 34 I/O30 (io), 35 I/O31 (io), 41 I/O32 (io), 42 I/O33 (io), 43 I/O34 (io), 44 I/O35 (io), 45 I/O36 (io), 46 I/O37 (io), 47 I/O38 (io), 48 I/O39 (io), 53 I/O40 (io), 54 I/O41 (io), 55 I/O42 (io), 56 I/O43 (io), 57 I/O44 (io), 58 I/O45 (io), 59 I/O46 (io), 60 I/O47 (io), 66 I/O48 (io), 67 I/O49 (io), 68 I/O50 (io), 69 I/O51 (io), 70 I/O52 (io), 71 I/O53 (io), 72 I/O54 (io), 73 I/O55 (io), 78 I/O56 (io), 79 I/O57 (io), 80 I/O58 (io), 81 I/O59 (io), 82 I/O60 (io), 83 I/O61 (io), 84 I/O62 (io), 85 I/O63 (io), 91 I/O0 (io), 92 I/O1 (io), 93 I/O2 (io), 94 I/O3 (io), 95 I/O4 (io), 96 I/O5 (io), 97 I/O6 (io), 98 I/O7 (io)
part B pins: 1 TCK (in), 2 GND (power), 11 CLK0/IN0 (in), 12 VCCO (power), 13 NC, 14 GND (power), 15 CLK1/IN1 (in), 24 VCCO (power), 25 NC, 26 TMS (in), 27 GND (power), 36 IN2 (in), 37 VCCO (power), 38 NC, 39 GND (power), 40 VCC (power), 49 VCCO (power), 50 TDO (out), 51 NC, 52 GND (power), 61 CLK2/IN3 (in), 62 VCCO (power), 63 NC, 64 GND (power), 65 CLK3/IN4 (in), 74 VCCO (power), 75 TDI (in), 76 NC, 77 GND (power), 86 NC, 87 VCC (power), 88 NC, 89 GND (power), 90 VCCO (power), 99 VCCO (power), 100 NC

## CY37128VP100-83BBC
designator U?
Ultra37000 3.3V, ISR High-Performance CPLD
footprint BB100 (BGA, 100-Leads, Body 11x11mm, Pitch 1mm)
3D model CY37128VP100-BB100 (100-Ball Thin Ball Grid Array 1 mm Pitch)
part A pins: A2 I/O9 (io), A3 I/O8 (io), A4 I/O6 (io), A5 I/O3 (io), A6 I/O76 (io), A7 I/O74 (io), A8 I/O72 (io), A9 I/O71 (io), A10 I/O70 (io), B1 I/O11 (io), B2 I/O10 (io), B3 I/O7 (io), B4 I/O5 (io), B5 I/O2 (io), B6 I/O77 (io), B8 I/O73 (io), B9 I/O68 (io), B10 I/O69 (io), C1 I/O12 (io), C2 I/O13/TCK (io), C4 I/O4 (io), C5 I/O1 (io), C6 I/O78 (io), C7 I/O75 (io), C9 I/O67/TDI (io), C10 I/O66 (io), D1 I/O14 (io), D3 I/O15 (io), D4 I/O16 (io), D5 I/O0 (io), D6 I/O79 (io), D7 I/O63 (io), D8 I/O64 (io), D10 I/O65 (io), E1 I/O17 (io), E3 I/O18 (io), E4 I/O19 (io), E7 I/O60 (io), E8 I/O61 (io), E10 I/O62 (io), F1 I/O22 (io), F3 I/O21 (io), F4 I/O20 (io), F7 I/O59 (io), F8 I/O58 (io), F10 I/O57 (io), G1 I/O27 (io), G3 I/O26 (io), G4 I/O24 (io), G5 I/O23 (io), G6 I/O56 (io), G7 I/O55 (io), G8 I/O54 (io), G10 I/O53 (io), H1 I/O28 (io), H2 I/O33/TMS (io), H4 I/O25 (io), H5 I/O39 (io), H6 I/O40 (io), H7 I/O52 (io), H9 I/O47/TDO (io), H10 I/O51 (io), J1 I/O29 (io), J2 I/O32 (io), J3 I/O35 (io), J5 I/O38 (io), J6 I/O41 (io), J7 I/O43 (io), J8 I/O45 (io), J9 I/O48 (io), J10 I/O50 (io), K1 I/O30 (io), K2 I/O31 (io), K3 I/O34 (io), K4 I/O36 (io), K5 I/O37 (io), K6 I/O42 (io), K7 I/O44 (io), K8 I/O46 (io), K9 I/O49 (io)
part B pins: A1 NC, B7 VCC (power), C3 VCC (power), C8 VCC (power), D2 VCC (power), D9 CLK3/IN4 (in), E2 CLK0/IN0 (in), E5 GND (power), E6 GND (power), E9 CLK2/IN3 (in), F2 JTAGEN (in), F5 GND (power), F6 GND (power), F9 IN2 (in), G2 CLK1/IN1 (in), G9 VCC (power), H3 VCC (power), H8 VCC (power), J4 VCC (power), K10 NC

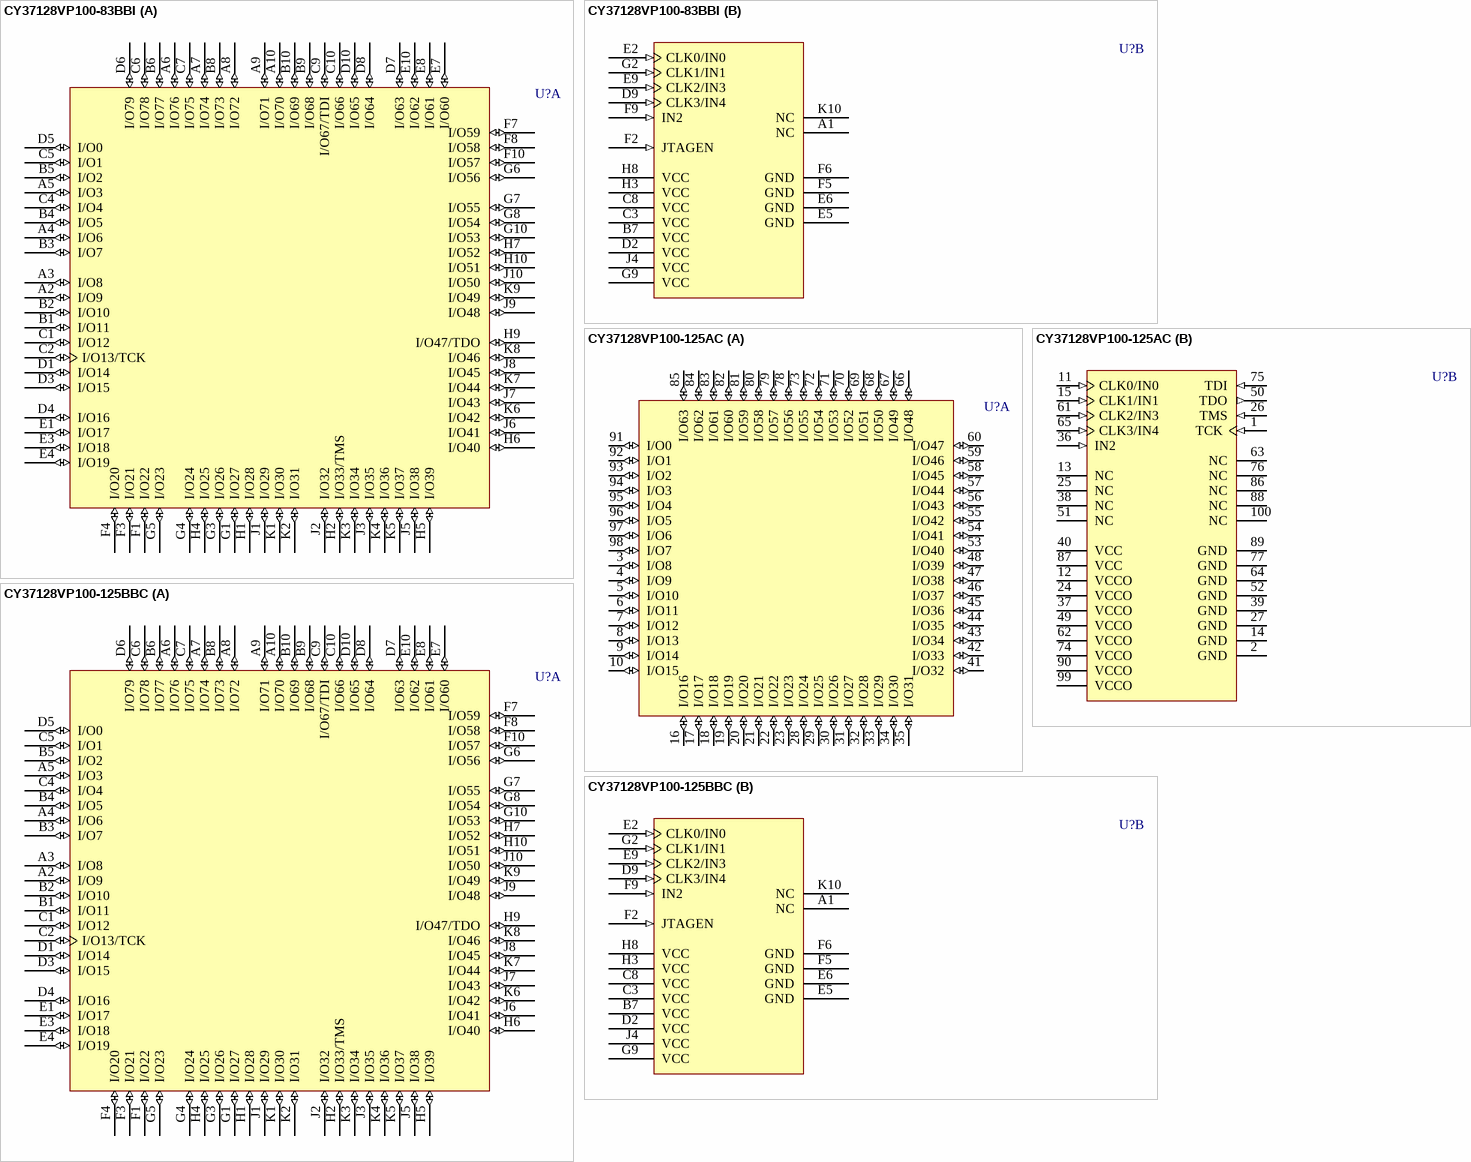
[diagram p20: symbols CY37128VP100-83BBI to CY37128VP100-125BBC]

## CY37128VP100-83BBI
designator U?
Ultra37000 3.3V, ISR High-Performance CPLD
footprint BB100 (BGA, 100-Leads, Body 11x11mm, Pitch 1mm)
3D model CY37128VP100-BB100 (100-Ball Thin Ball Grid Array 1 mm Pitch)
part A pins: A2 I/O9 (io), A3 I/O8 (io), A4 I/O6 (io), A5 I/O3 (io), A6 I/O76 (io), A7 I/O74 (io), A8 I/O72 (io), A9 I/O71 (io), A10 I/O70 (io), B1 I/O11 (io), B2 I/O10 (io), B3 I/O7 (io), B4 I/O5 (io), B5 I/O2 (io), B6 I/O77 (io), B8 I/O73 (io), B9 I/O68 (io), B10 I/O69 (io), C1 I/O12 (io), C2 I/O13/TCK (io), C4 I/O4 (io), C5 I/O1 (io), C6 I/O78 (io), C7 I/O75 (io), C9 I/O67/TDI (io), C10 I/O66 (io), D1 I/O14 (io), D3 I/O15 (io), D4 I/O16 (io), D5 I/O0 (io), D6 I/O79 (io), D7 I/O63 (io), D8 I/O64 (io), D10 I/O65 (io), E1 I/O17 (io), E3 I/O18 (io), E4 I/O19 (io), E7 I/O60 (io), E8 I/O61 (io), E10 I/O62 (io), F1 I/O22 (io), F3 I/O21 (io), F4 I/O20 (io), F7 I/O59 (io), F8 I/O58 (io), F10 I/O57 (io), G1 I/O27 (io), G3 I/O26 (io), G4 I/O24 (io), G5 I/O23 (io), G6 I/O56 (io), G7 I/O55 (io), G8 I/O54 (io), G10 I/O53 (io), H1 I/O28 (io), H2 I/O33/TMS (io), H4 I/O25 (io), H5 I/O39 (io), H6 I/O40 (io), H7 I/O52 (io), H9 I/O47/TDO (io), H10 I/O51 (io), J1 I/O29 (io), J2 I/O32 (io), J3 I/O35 (io), J5 I/O38 (io), J6 I/O41 (io), J7 I/O43 (io), J8 I/O45 (io), J9 I/O48 (io), J10 I/O50 (io), K1 I/O30 (io), K2 I/O31 (io), K3 I/O34 (io), K4 I/O36 (io), K5 I/O37 (io), K6 I/O42 (io), K7 I/O44 (io), K8 I/O46 (io), K9 I/O49 (io)
part B pins: A1 NC, B7 VCC (power), C3 VCC (power), C8 VCC (power), D2 VCC (power), D9 CLK3/IN4 (in), E2 CLK0/IN0 (in), E5 GND (power), E6 GND (power), E9 CLK2/IN3 (in), F2 JTAGEN (in), F5 GND (power), F6 GND (power), F9 IN2 (in), G2 CLK1/IN1 (in), G9 VCC (power), H3 VCC (power), H8 VCC (power), J4 VCC (power), K10 NC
